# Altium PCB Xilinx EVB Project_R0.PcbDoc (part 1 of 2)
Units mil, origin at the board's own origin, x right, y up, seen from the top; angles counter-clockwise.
Board outline 8120 x 5778 mil, 6 copper layers (Top Layer, Mid-Layer 1, Mid-Layer 2, Mid-Layer 3, Mid-Layer 4, Bottom Layer); 283 components, 125 nets, 1037 pads, 1290 vias.
Unrouted connection lines stored in the file: 1.
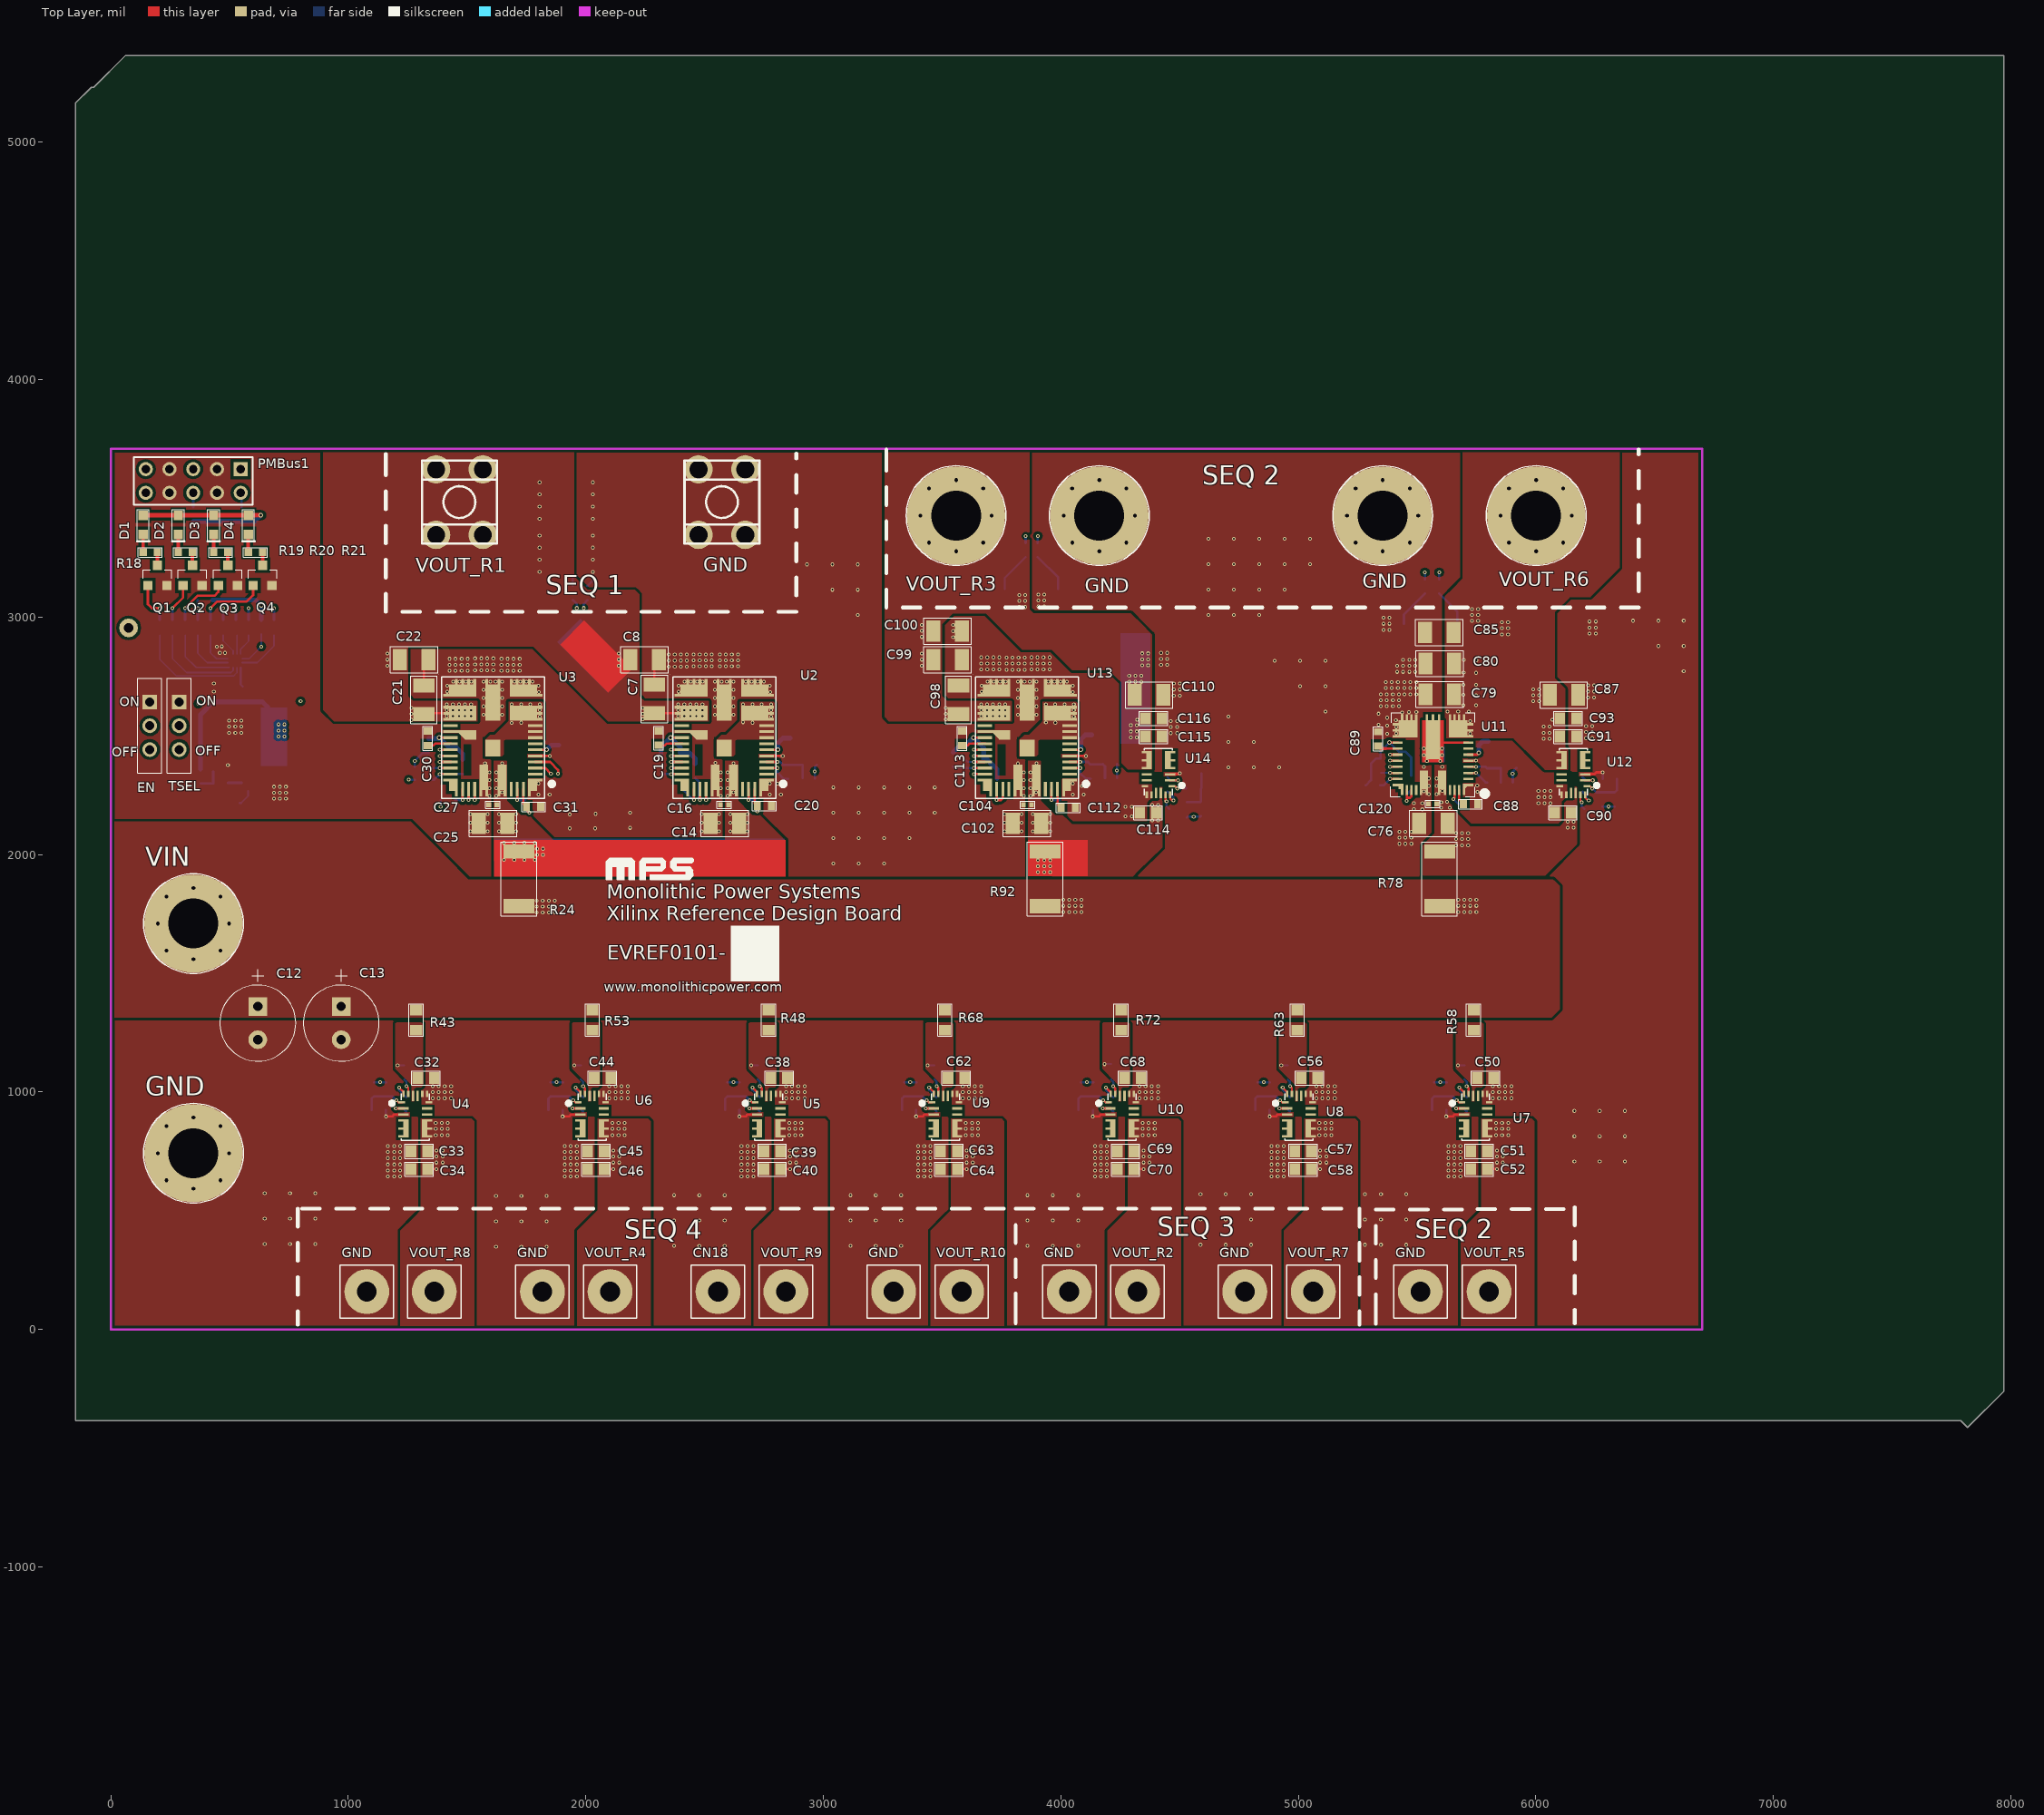
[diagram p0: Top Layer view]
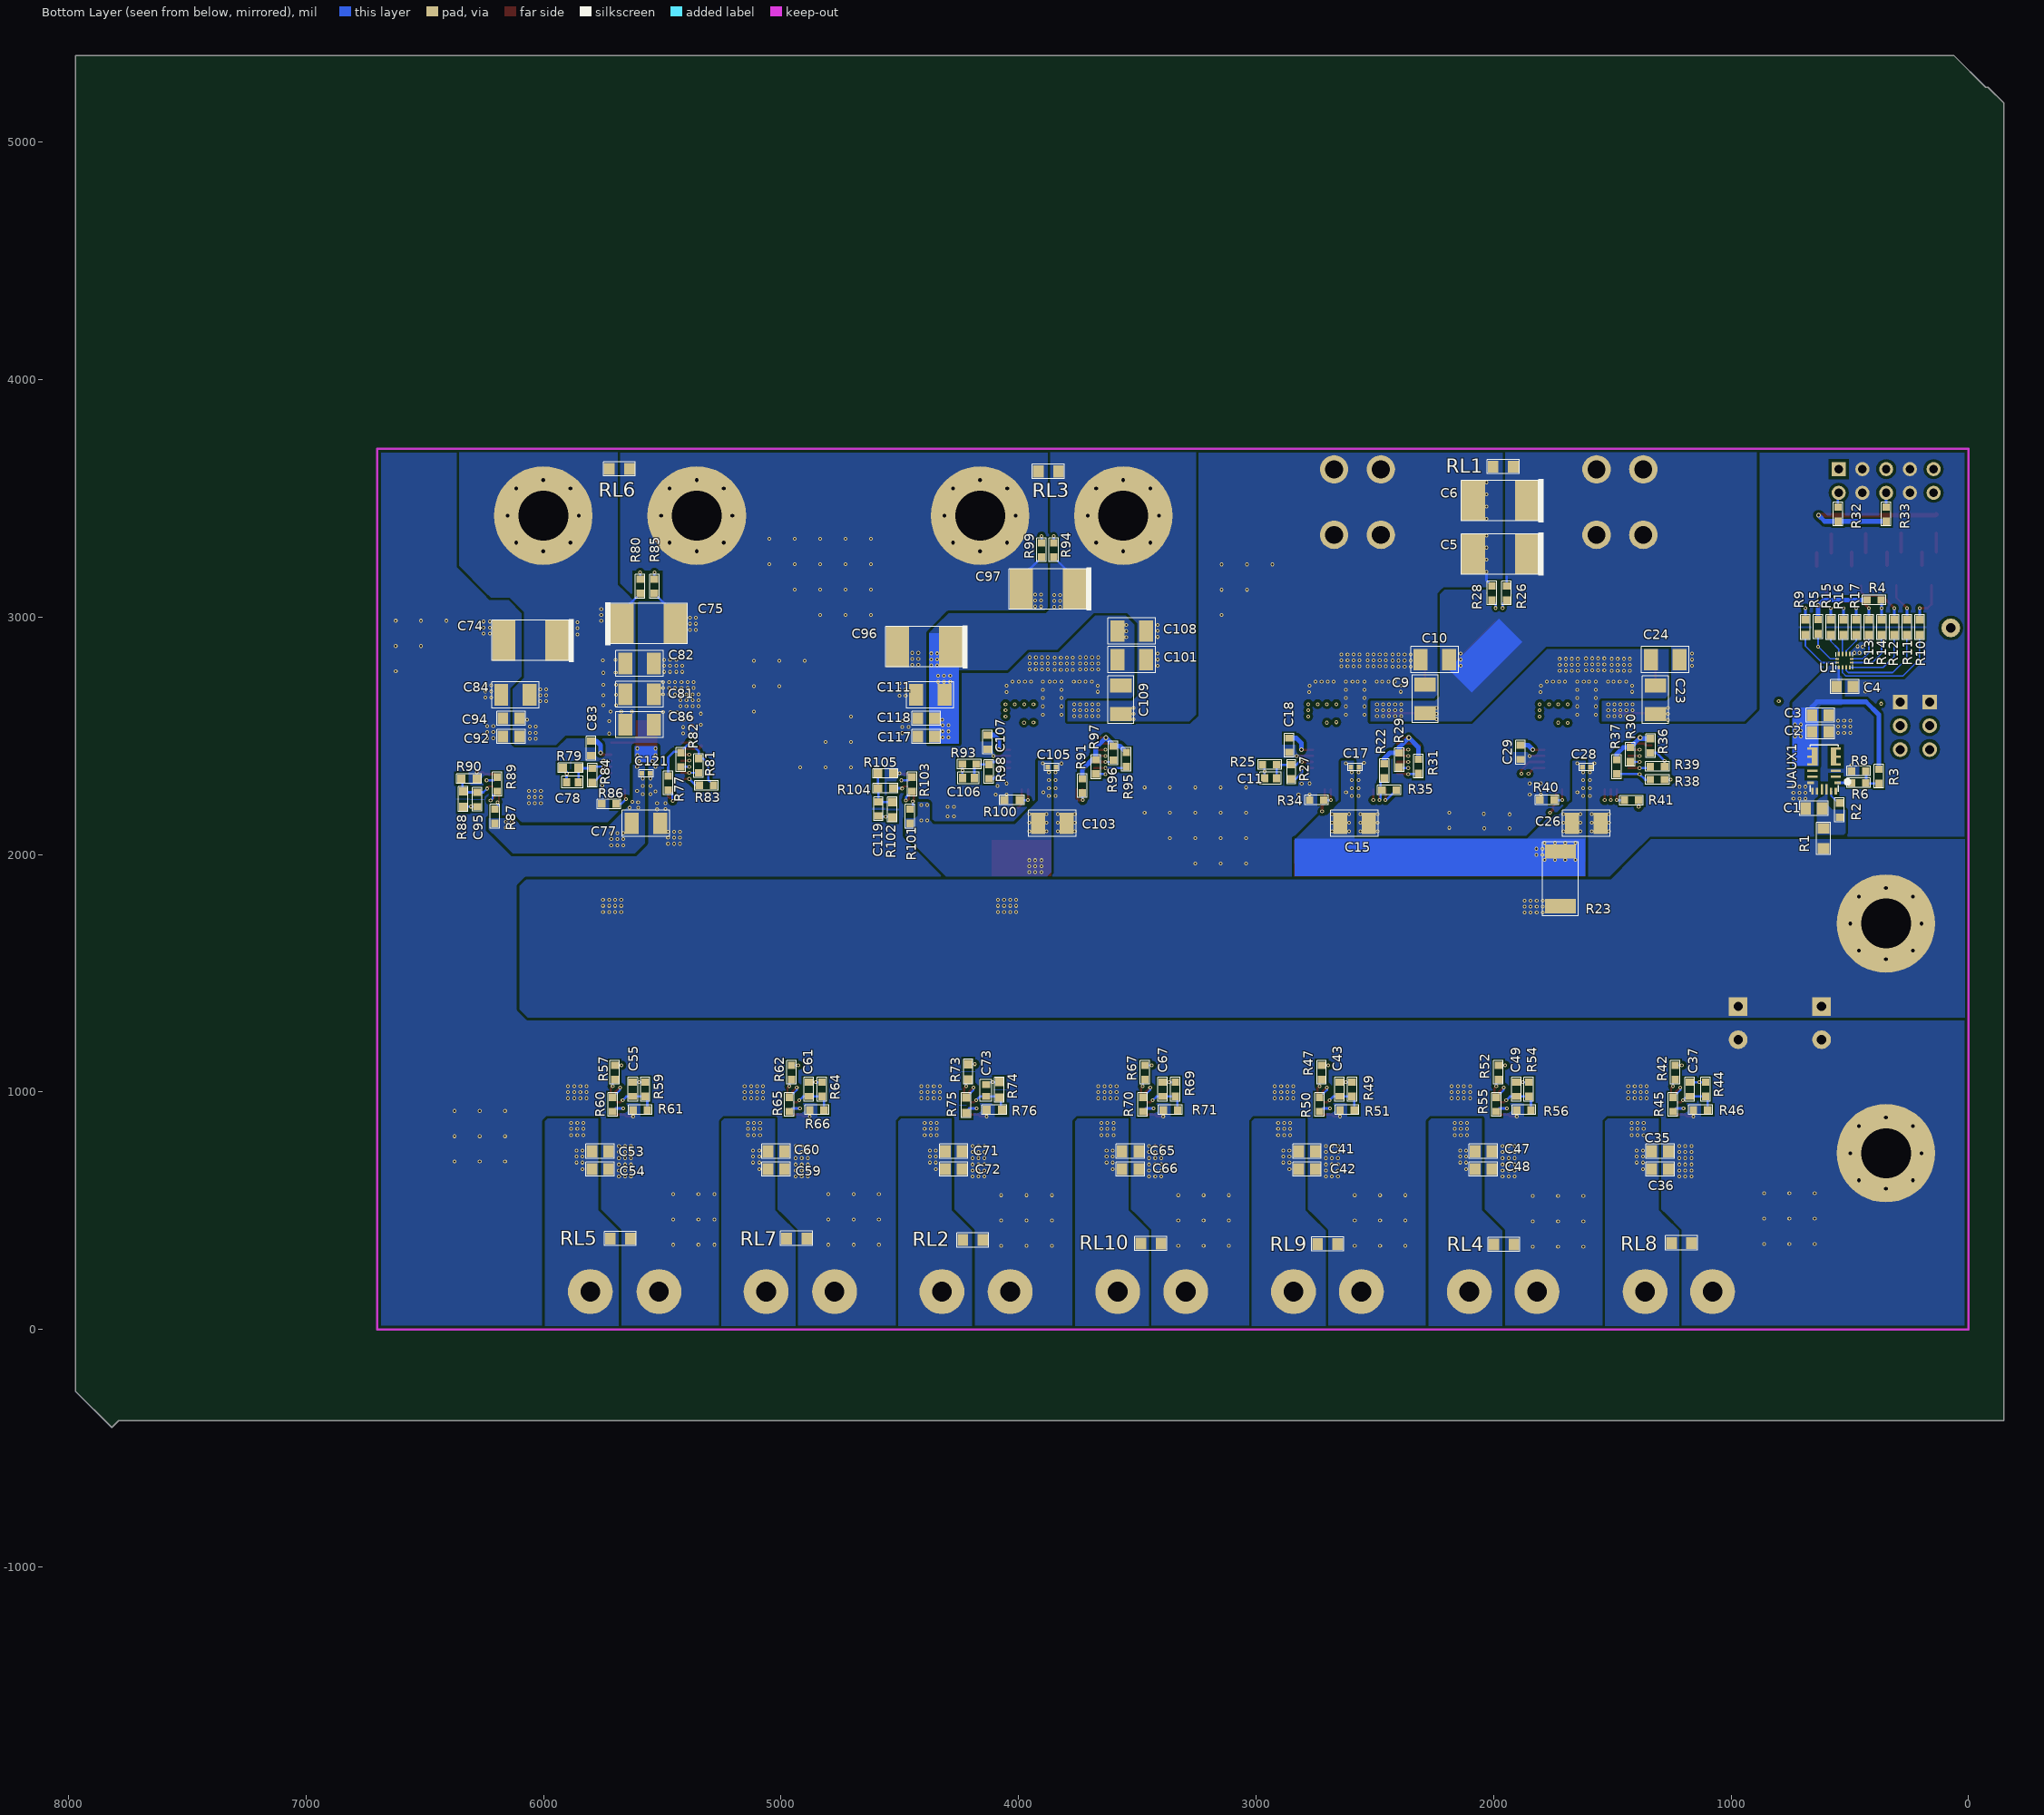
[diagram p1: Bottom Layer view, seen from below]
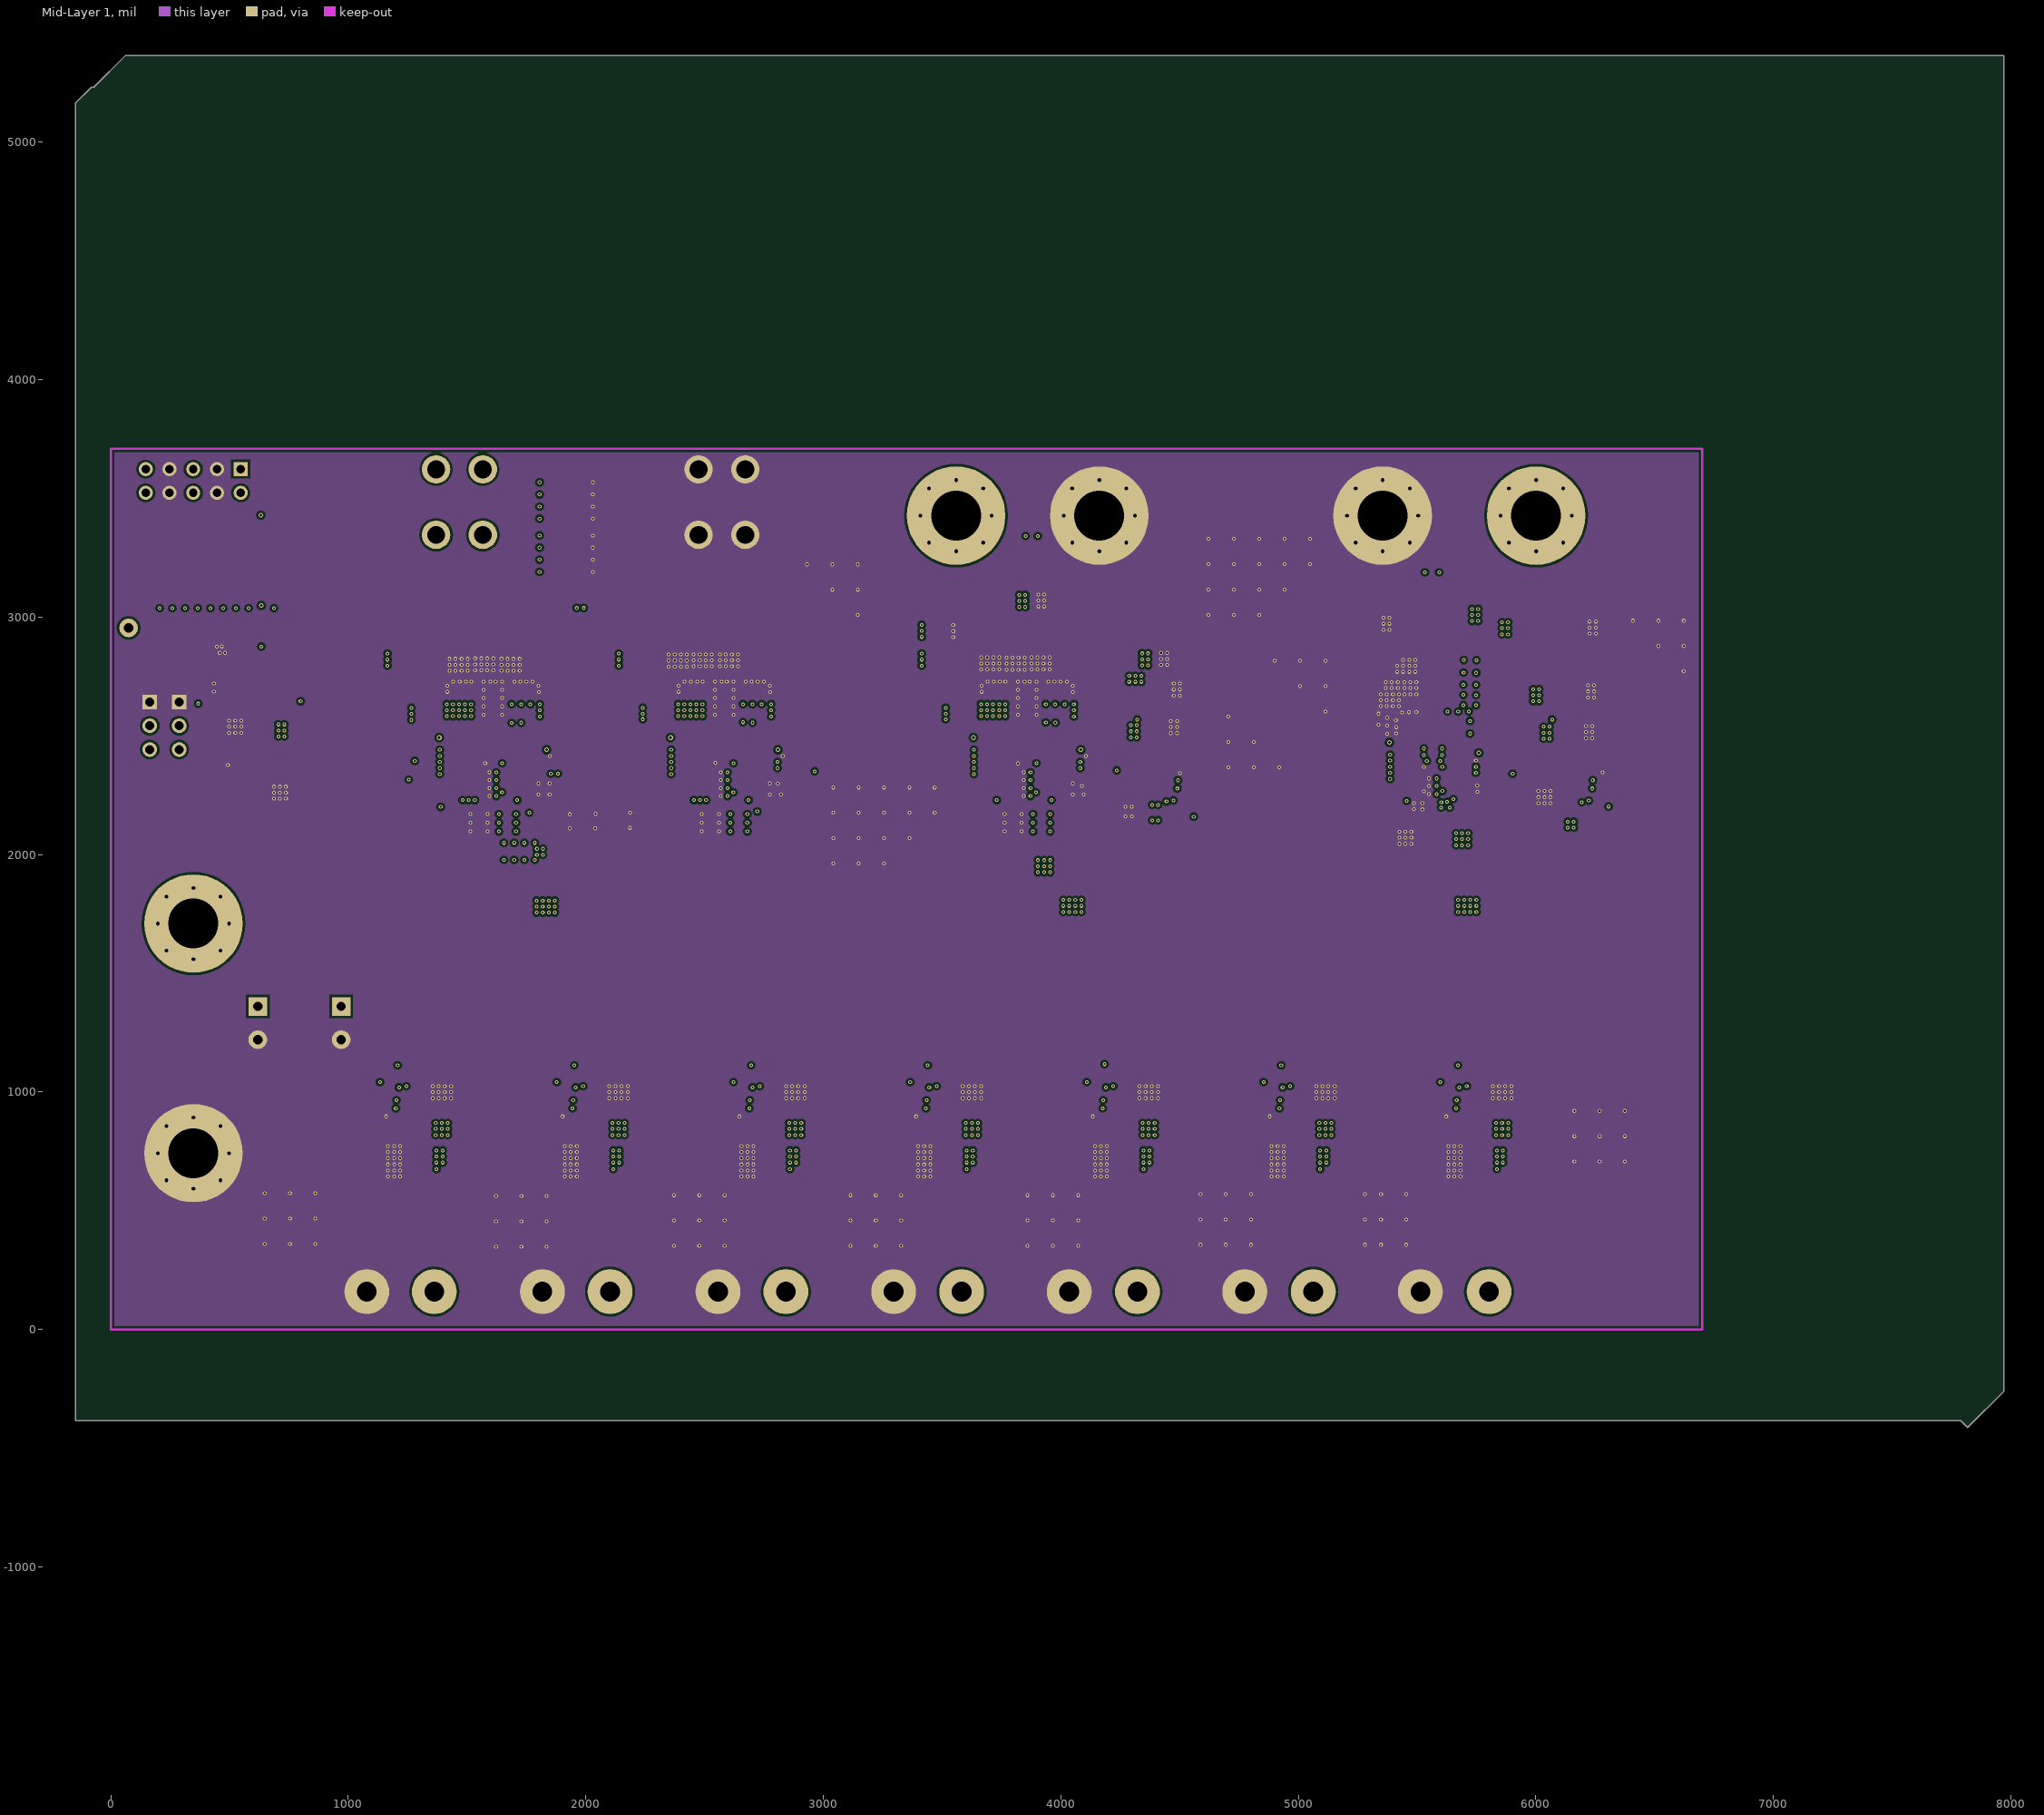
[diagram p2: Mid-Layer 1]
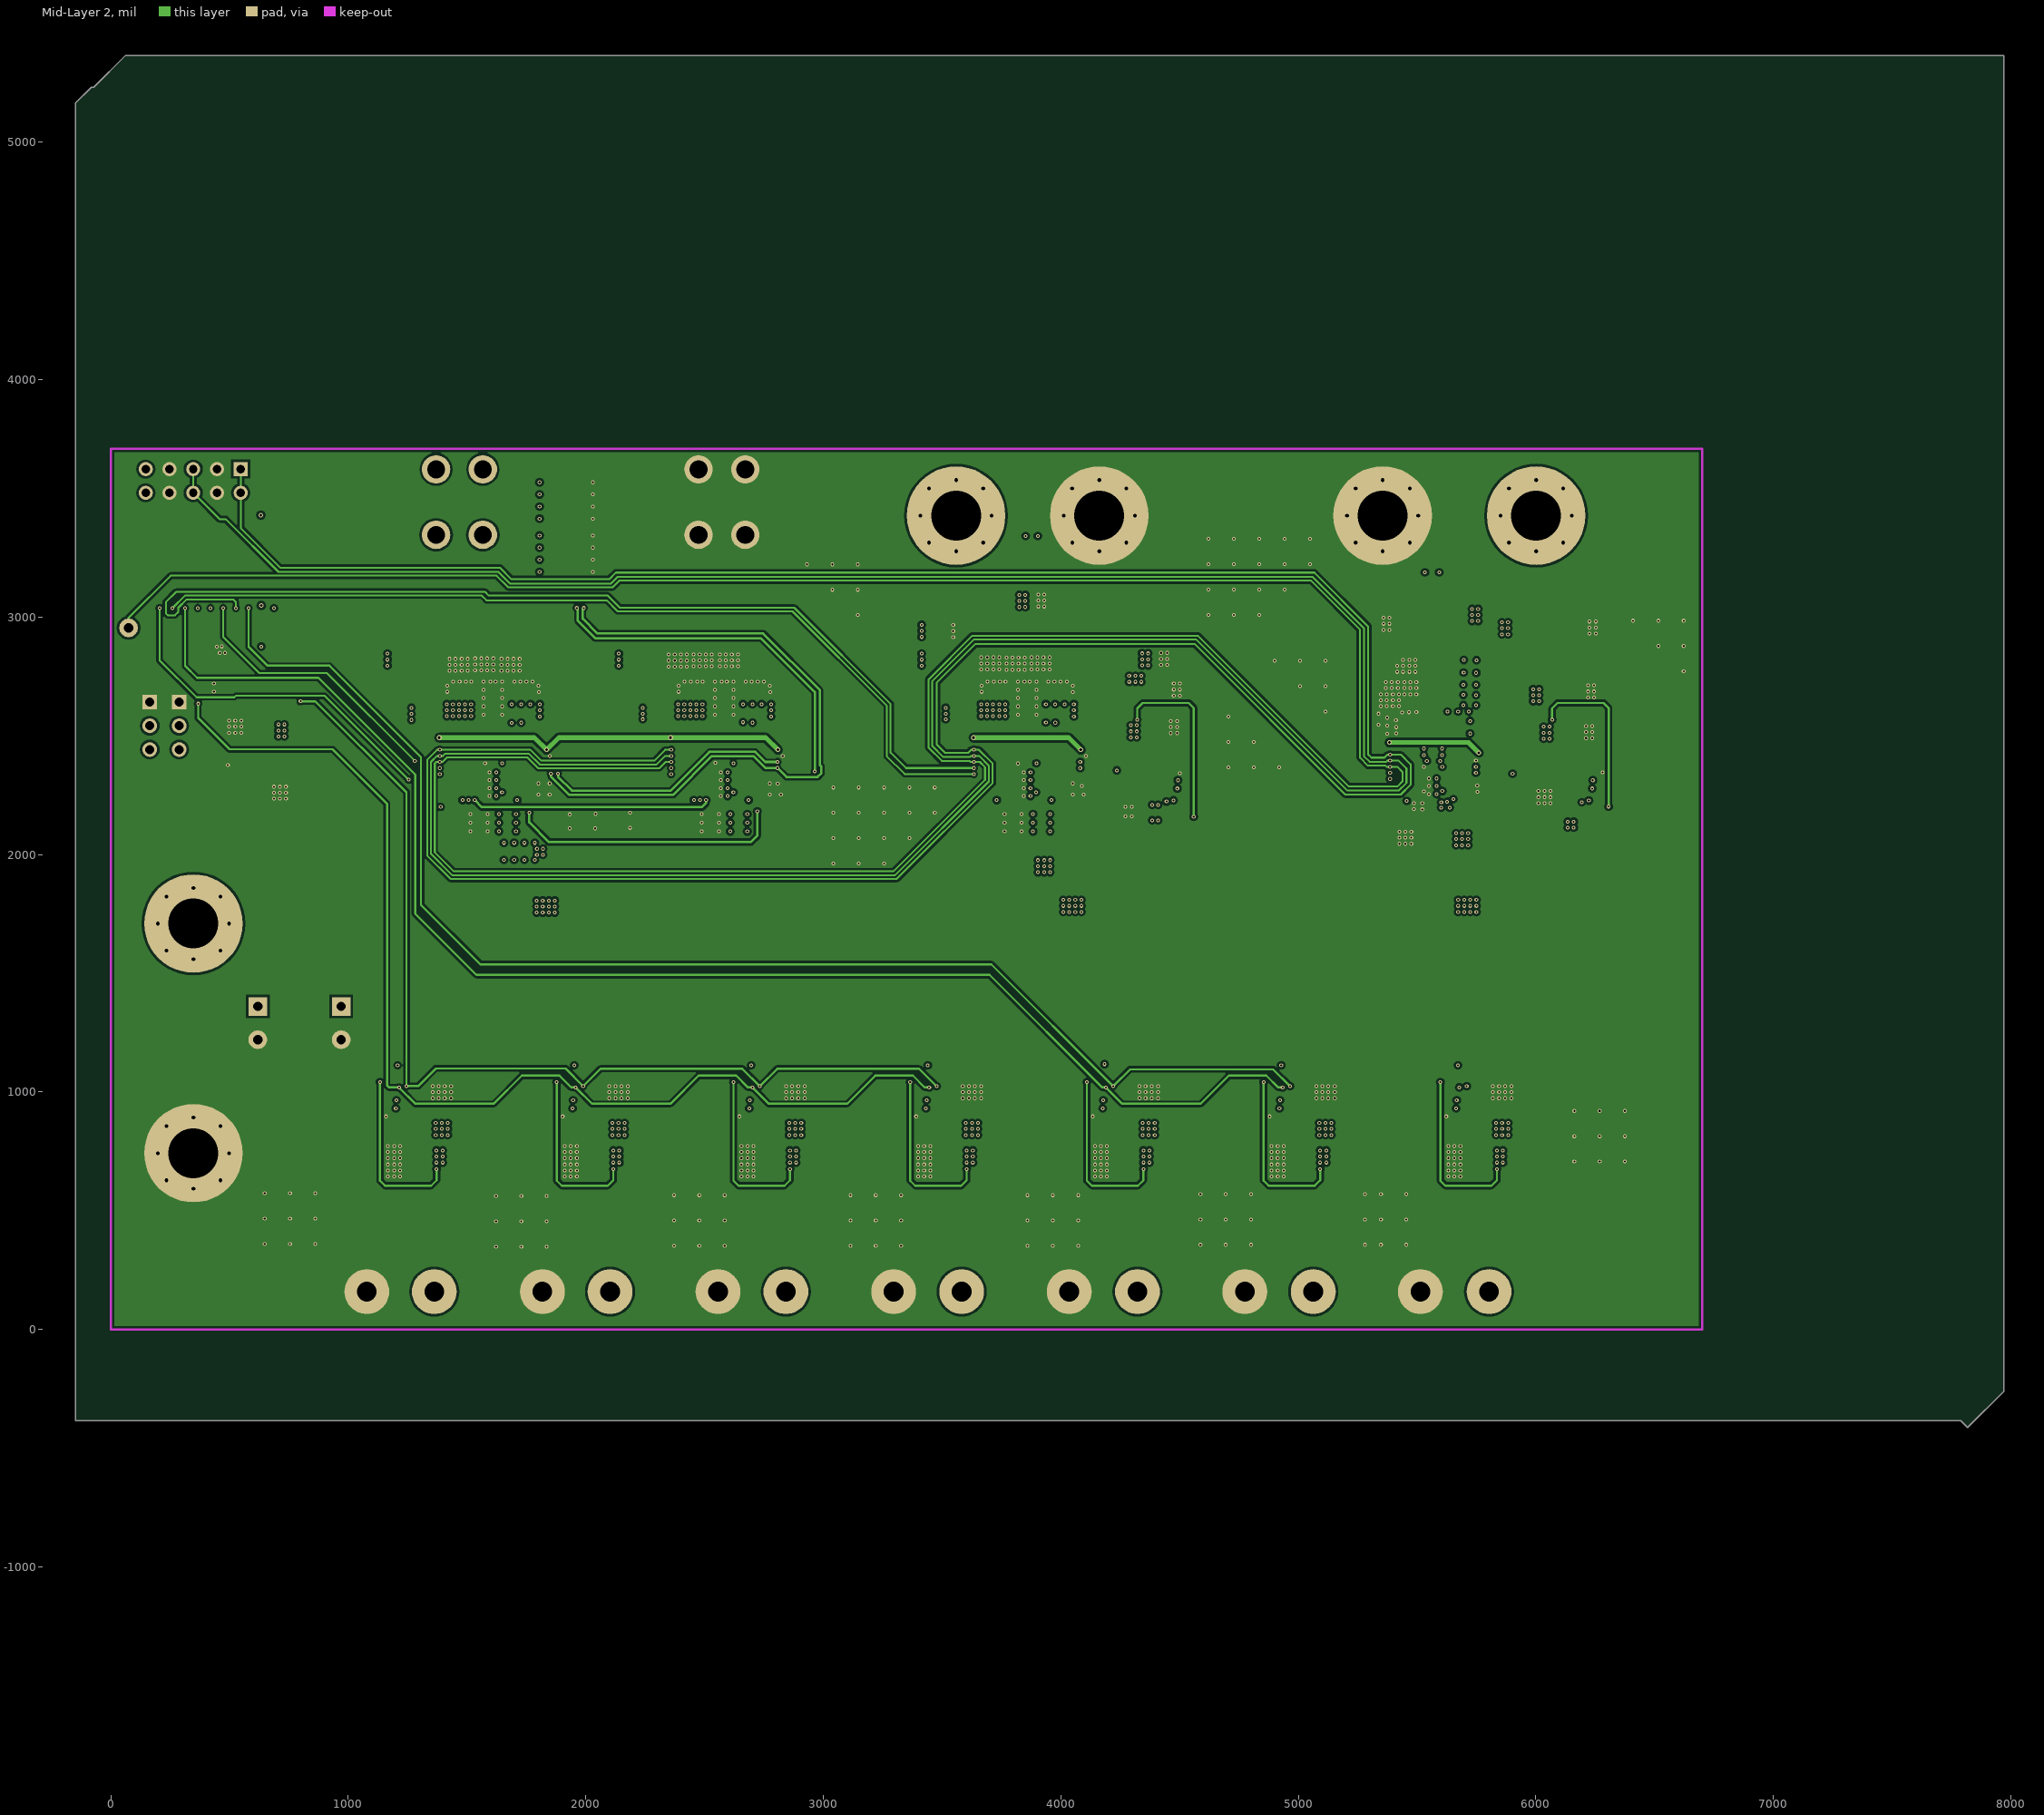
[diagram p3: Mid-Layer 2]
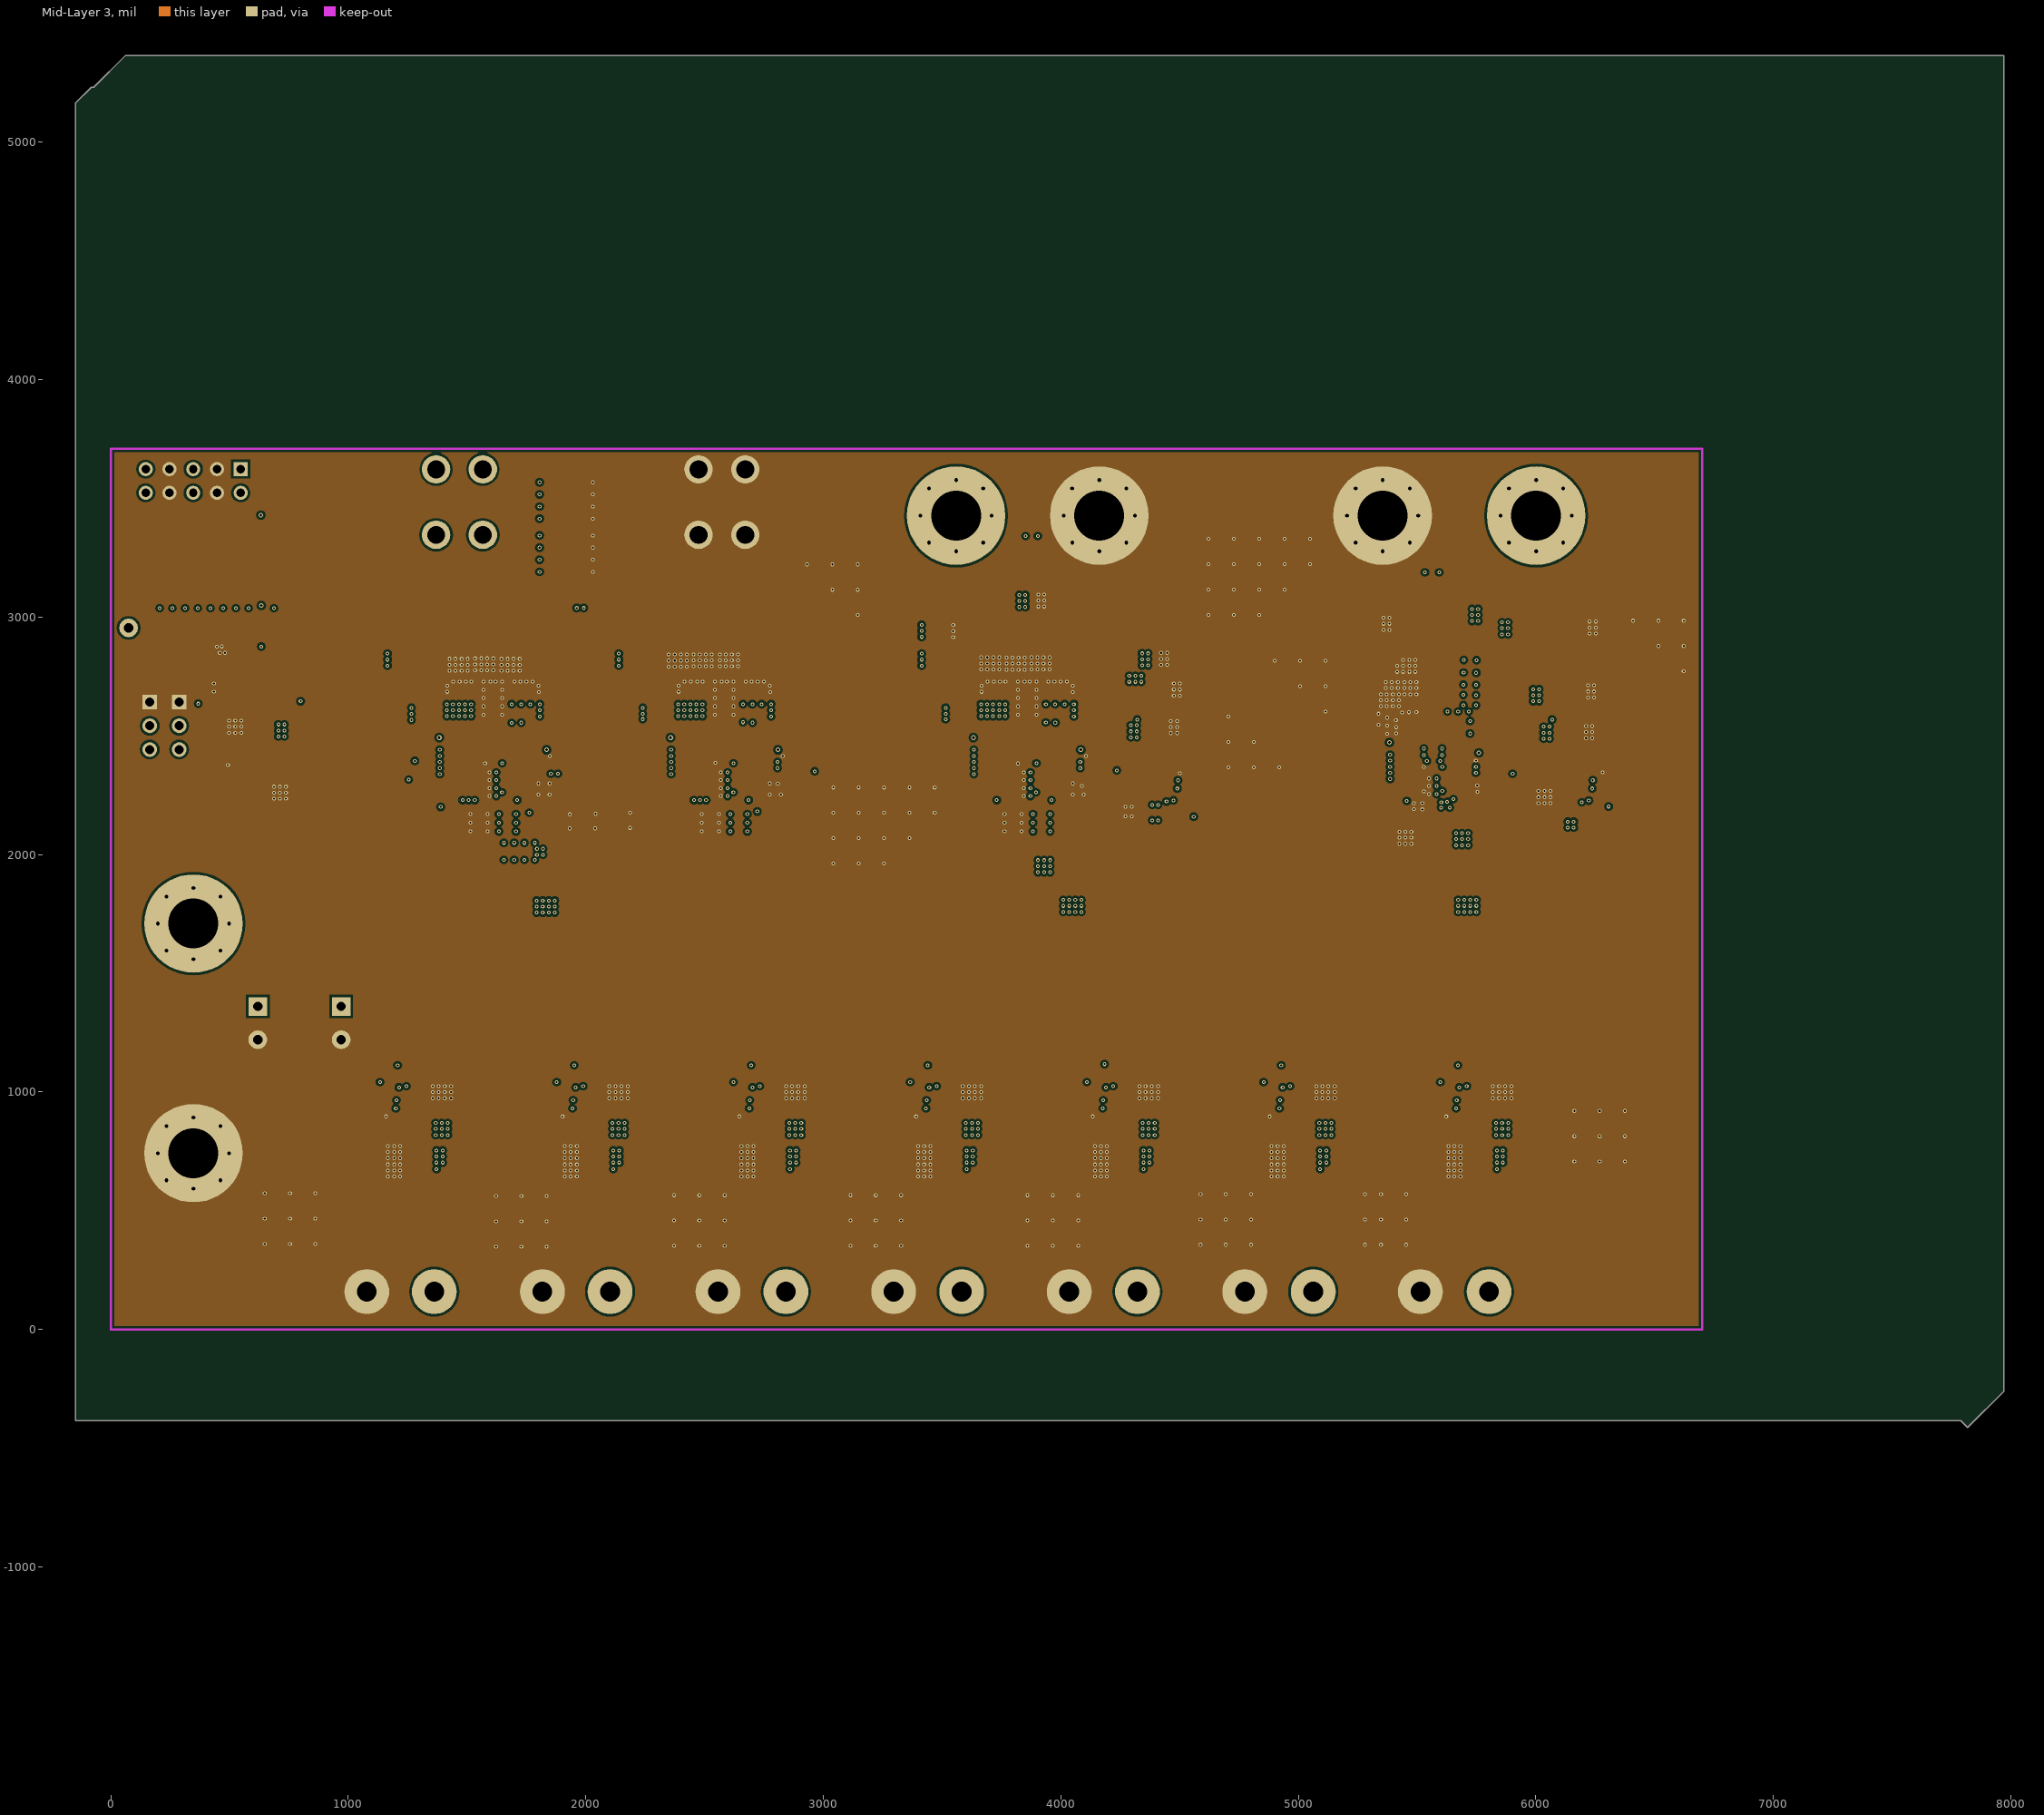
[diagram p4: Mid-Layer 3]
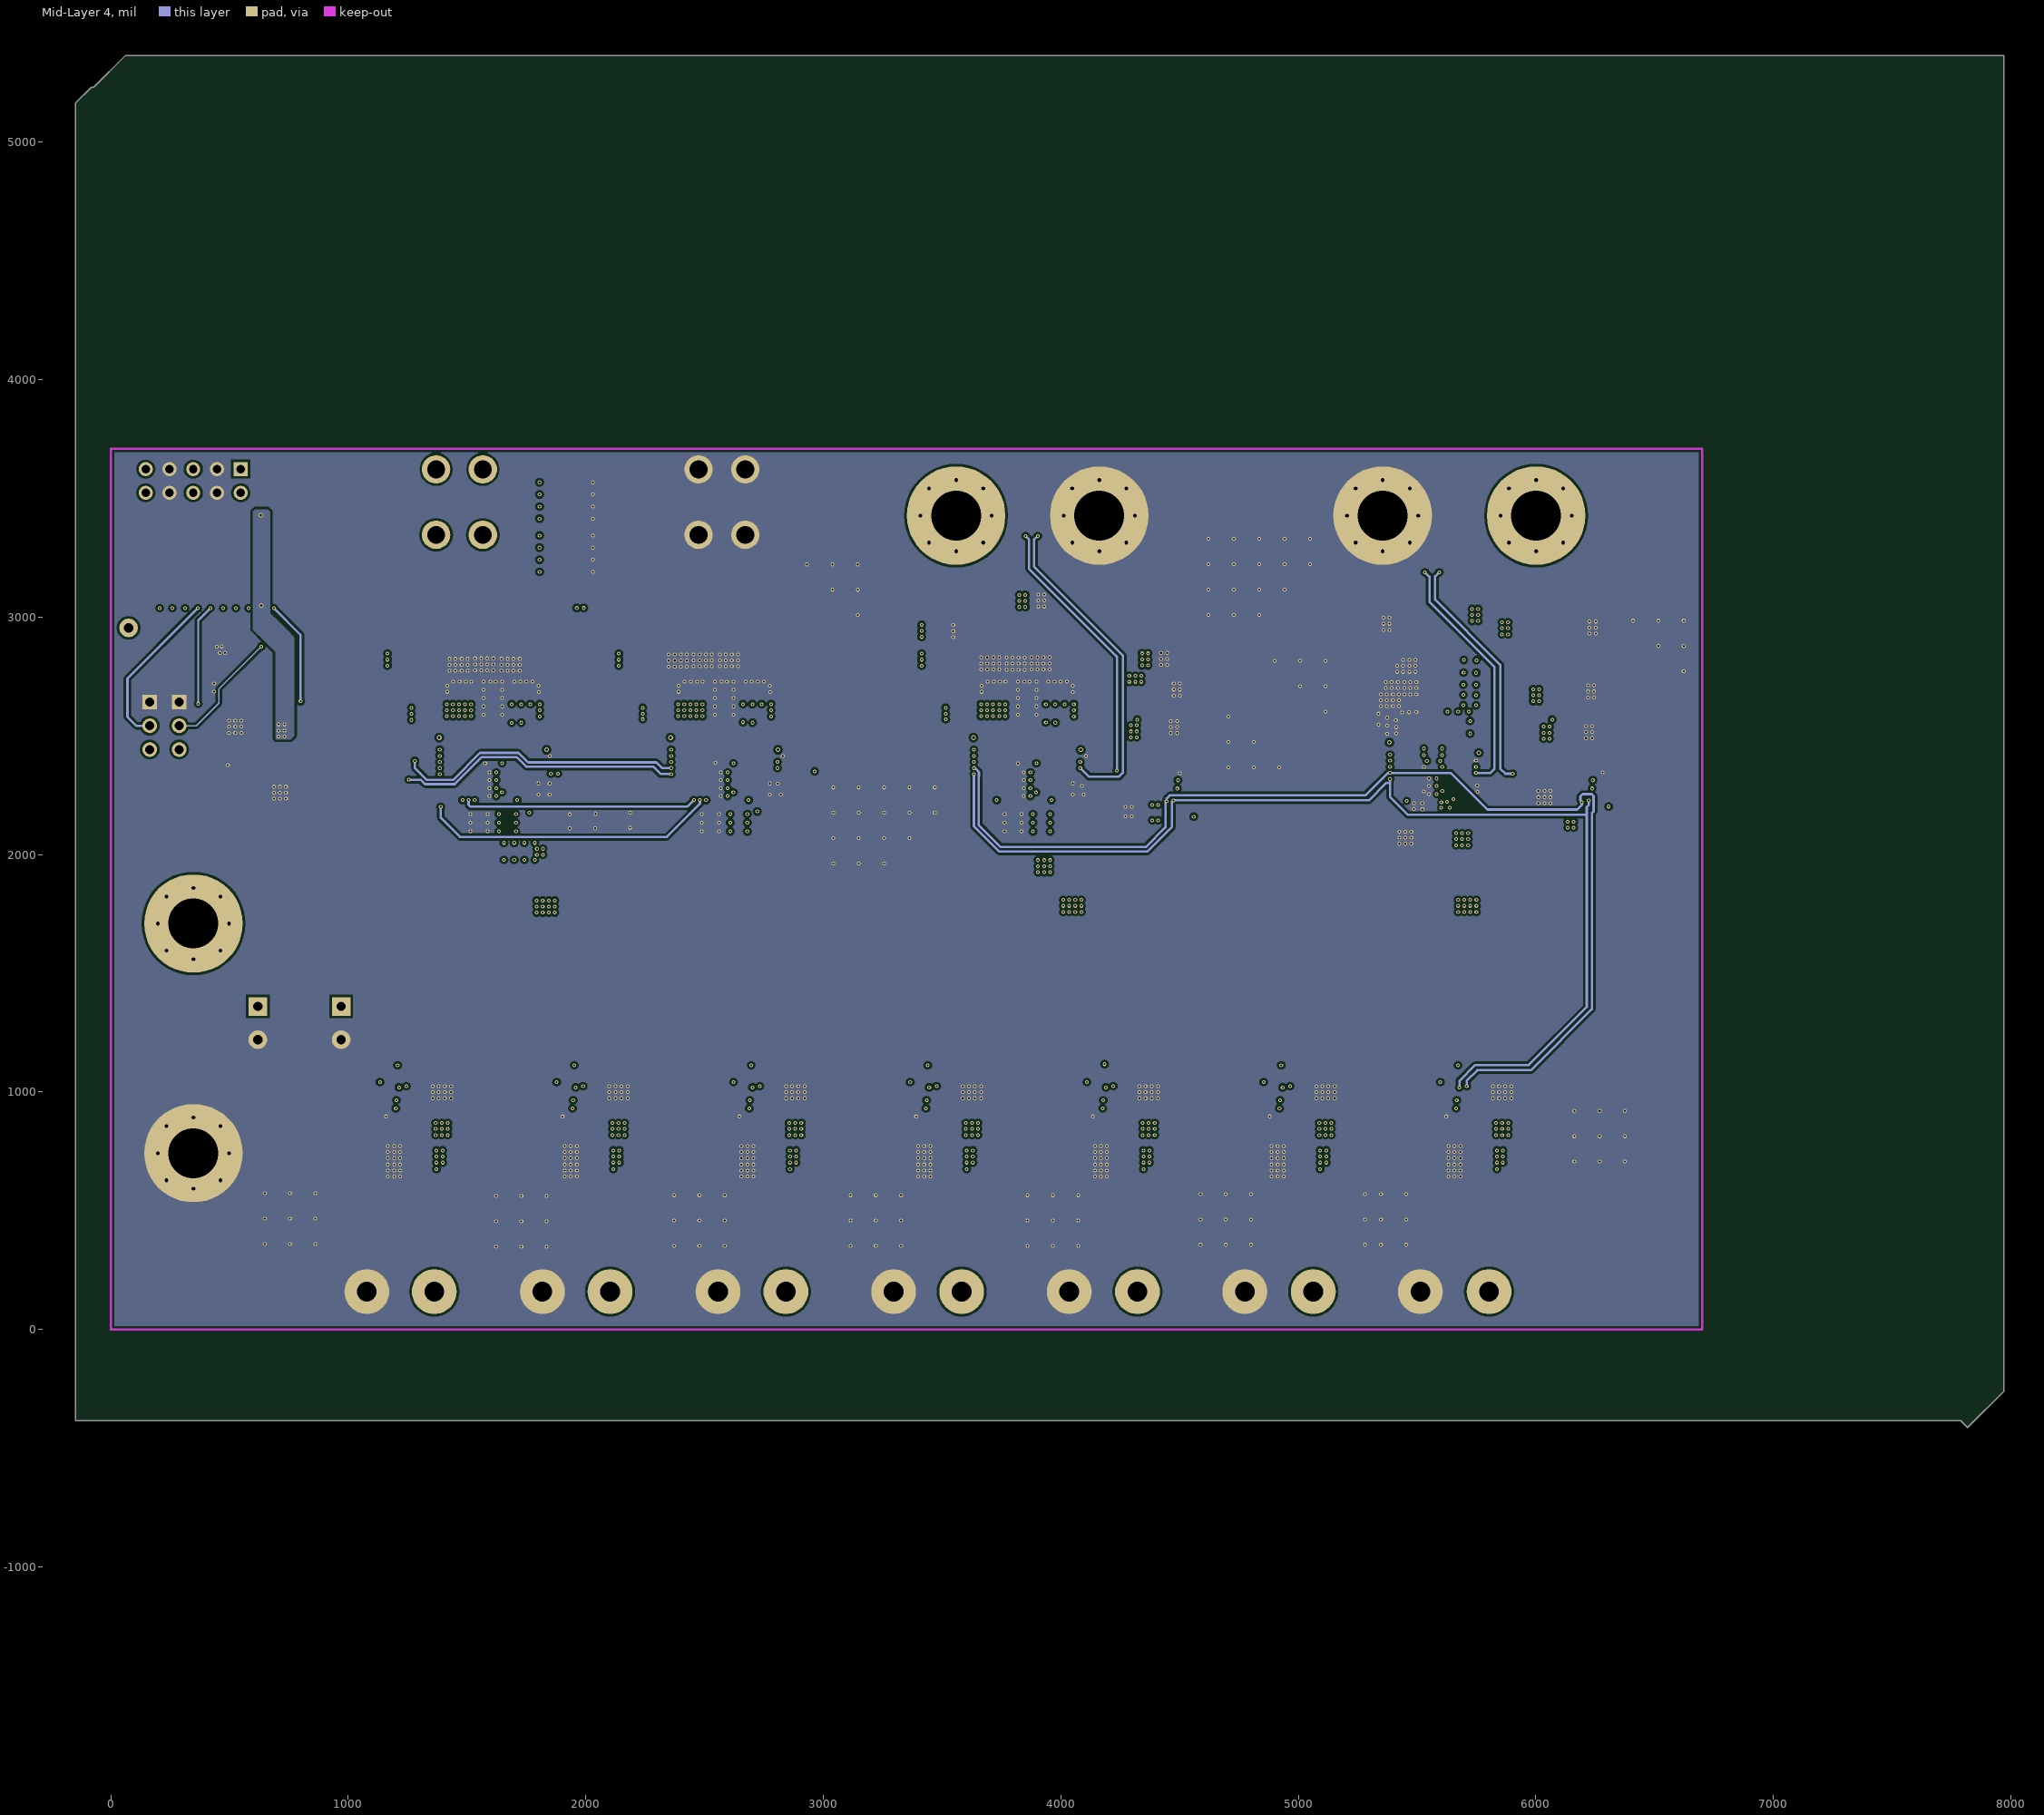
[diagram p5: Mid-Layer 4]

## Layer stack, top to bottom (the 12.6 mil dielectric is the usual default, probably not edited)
Top Layer: signal copper 1.4
Dielectric: core 12.6, FR-4, Dk 4.8
Mid-Layer 1: signal copper 1.4
Dielectric: prepreg 12.6, FR-4, Dk 4.8
Mid-Layer 2: signal copper 1.4
Dielectric: core 12.6, FR-4, Dk 4.8
Mid-Layer 3: signal copper 1.4
Dielectric: prepreg 12.6, FR-4, Dk 4.8
Mid-Layer 4: signal copper 1.4
Dielectric: core 12.6, FR-4, Dk 4.8
Bottom Layer: signal copper 1.4

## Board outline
-82,5230.9 -149,5163.9 -149,-384.1 7789,-384.1 7818,-413.1 7971,-260.1 7971,5364.9 62,5364.9 -72,5230.9

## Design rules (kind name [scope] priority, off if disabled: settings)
Clearance [All] p1: gap=7
ComponentClearance [All] p1: gap=0 collisioncheckmode=3 verticalgap=0 showdistances=FALSE
HoleSize [All] p1: absolutevalues=TRUE maxlimit=10000 minlimit=1 maxpercent=80.000 minpercent=20.000
HoleToHoleClearance [All] p1: gap=0 allowstackedmicrovias=TRUE
MinimumSolderMaskSliver [All] p1: minsoldermaskwidth=0
PlaneConnect [All] p1: planeconnectstyle=Direct reliefexpansion=20 reliefentries=4 reliefconductorwidth=10 reliefairgap=10
PolygonConnect [All] p1: connectstyle=Direct reliefconductorwidth=10 reliefentries=4 polygonreliefangle="90 Angle"
RoutingVias [All] p1: holewidth=10 width=20 viastyle="Through Hole" minholewidth=10 minwidth=20 maxholewidth=10 maxwidth=500
SilkToSilkClearance [All] p1: silktosilkclearance=0
SilkscreenOverComponentPads [All] p1: minsilkscreentomaskgap=0
SolderMaskExpansion [All] p1: expansion=2
Width [All] p1: maxlimit=100 minlimit=3 preferedwidth=10
21 further rules are at their usual default settings.

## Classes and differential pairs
component class P5_Rail_6: C74 C75 C76 C77 C78 C79 C80 C81 C82 C83 C84 C85 C86 C87 C88 C89 C90 C91 C92 C93 C94 C95 C120 C121 GND R77 R78 R79 R80 R81 R82 R83 R84 R85 R86 R87 R88 R89 R90 U11 U12 VOUT_R6
component class P1_Rail1: C5 C6 C7 C8 C9 C10 C11 C12 C13 C14 C15 C16 C17 C18 C19 C20 C21 C22 C23 C24 C25 C26 C27 C28 C29 C30 C31 GND PMBus1 R22 R23 R24 R25 R26 R27 R28 R29 R30 R31 R32 R33 R34 R35 R36 R37 R38 R39 R40 R41 U2 U3 VIN VOUT_R1
component class P2_Rail_2: C68 C69 C70 C71 C72 C73 CN18 R72 R73 R74 R75 R76 U10 VOUT_R2
component class P4_Rail_4_and_Rail_5: C44 C45 C46 C47 C48 C49 C50 C51 C52 C53 C54 C55 GND R52 R53 R54 R55 R56 R57 R58 R59 R60 R61 U6 U7 VOUT_R4 VOUT_R5
component class P6_Rail_7_and_Rail_10: C56 C57 C58 C59 C60 C61 C62 C63 C64 C65 C66 C67 GND R62 R63 R64 R65 R66 R67 R68 R69 R70 R71 U8 U9 VOUT_R7 VOUT_R10
component class P7_Rail_8_and_Rail_9: C32 C33 C34 C35 C36 C37 C38 C39 C40 C41 C42 C43 GND R42 R43 R44 R45 R46 R47 R48 R49 R50 R51 U4 U5 VOUT_R8 VOUT_R9
component class P8_Aux_Circuit: C1 C2 C3 C4 D1 D2 D3 D4 EN Q1 Q2 Q3 Q4 R1 R2 R3 R4 R5 R6 R8 R9 R10 R11 R12 R13 R14 R15 R16 R17 R18 R19 R20 R21 RL1 RL2 RL3 RL4 RL5 RL6 RL7 RL8 RL9 RL10 TSEL U1 UAUX1
component class "P3_Rail 3": C96 C97 C98 C99 C100 C101 C102 C103 C104 C105 C106 C107 C108 C109 C110 C111 C112 C113 C114 C115 C116 C117 C118 C119 GND R91 R92 R93 R94 R95 R96 R97 R98 R99 R100 R101 R102 R103 R104 R105 U13 U14 VOUT_R7

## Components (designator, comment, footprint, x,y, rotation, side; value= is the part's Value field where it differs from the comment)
C1 "22uF/CAP0805" CAP0805 686,2194 r180 bottom
C2 "NS" CAP0805 589,2516 r0 bottom
C3 "22uF/CAP0805" CAP0805 589,2586 r0 bottom
C4 "22uF/CAP0805" CAP0805 486,2707 r0 bottom
C5 "POSCAP/D2-D4" POSCAP/D2 1861,3265 r0 bottom
C6 "POSCAP/D2-D4" POSCAP/D2 1861,3490 r0 bottom
C7 "100uF" CAP/1210 2289,2715 r270 top
C8 "100uF" CAP/1210 2308,2820 r180 top
C9 "100uF" CAP/1210 2289,2715 r270 bottom
C10 "100uF" CAP/1210 2308,2820 r180 bottom
C11 "4.7nF" CAP0603 2914,2321 r0 bottom
C12 "220uF" CAP/OD8.0P3.5 619,1360 r270 top
C13 "220uF" CAP/OD8.0P3.5 970,1360 r270 top
C14 "22uF" CAP/1210 2525,2131 r0 top
C15 "22uF" CAP/1210 2525,2131 r0 bottom
C16 "0.1uF" CAP0402 2566,2209 r0 top
C17 "0.1uF" CAP0402 2566,2368 r0 bottom
C18 "5.6pF/CAP0603" CAP/0603 2861,2430 r90 bottom
C19 "4.7uF" CAP/0603 2307,2520 r270 top
C20 "1uF" CAP/0603 2782,2205 r180 top
C21 "100uF" CAP/1210 1318.64,2711.36 r270 top
C22 "100uF" CAP/1210 1337.64,2820 r180 top
C23 "100uF" CAP/1210 1318.64,2711.36 r270 bottom
C24 "100uF" CAP/1210 1337.64,2820 r180 bottom
C25 "22uF" CAP/1210 1550,2131 r0 top
C26 "22uF" CAP/1210 1550,2131 r0 bottom
C27 "0.1uF" CAP0402 1591,2209 r0 top
C28 "0.1uF" CAP0402 1591,2368 r0 bottom
C29 "4.7uF" CAP/0603 1886,2400 r90 bottom
C30 "5.6pF/CAP0603" CAP/0603 1335,2519 r270 top
C31 "5.6pF/CAP0603" CAP/0603 1810,2201 r180 top
C32 "22uF/CAP0805" CAP0805 1362,1058 r180 top
C33 "22uF/CAP0805" CAP0805 1264,750 r0 top
C34 "22uF/CAP0805" CAP0805 1264,675 r0 top
C35 "22uF/CAP0805" CAP0805 1264,750 r0 bottom
C36 "22uF/CAP0805" CAP0805 1264,675 r0 bottom
C37 "5.6pF/CAP0603" CAP/0603 1173.5,981 r90 bottom
C38 "22uF/CAP0805" CAP0805 2849,1059 r180 top
C39 "NS" CAP0805 2750,750 r0 top
C40 "22uF/CAP0805" CAP0805 2750,675 r0 top
C41 "NS" CAP0805 2750,750 r0 bottom
C42 "NS" CAP0805 2750,675 r0 bottom
C43 "5.6pF/CAP0603" CAP/0603 2648.67,981 r90 bottom
C44 "22uF/CAP0805" CAP0805 2105,1058 r180 top
C45 "Cap" CAP0805 2008,750 r0 top
C46 "22uF" CAP0805 2008,675 r0 top
C47 "Cap" CAP0805 2008,750 r0 bottom
C48 "Cap" CAP0805 2008,675 r0 bottom
C49 "5.6pF/CAP0603" CAP/0603 1904.58,981 r90 bottom
C50 "22uF/CAP0805" CAP0805 5823,1058 r180 top
C51 "NS" CAP0805 5726,750 r0 top
C52 "NS" CAP0805 5726,675 r0 top
C53 "22uF/CAP0805" CAP0805 5726,750 r0 bottom
C54 "NS" CAP0805 5726,675 r0 bottom
C55 "5.6pF/CAP0603" CAP/0603 5625,981 r90 bottom
C56 "22uF/CAP0805" CAP0805 5082,1058 r180 top
C57 "NS" CAP0805 4985,750 r0 top
C58 "22uF/CAP0805" CAP0805 4985,675 r0 top
C59 "NS" CAP0805 4985,675 r0 bottom
C60 "NS" CAP0805 4985,750 r0 bottom
C61 "5.6pF/CAP0603" CAP/0603 4883,981 r90 bottom
C62 "22uF/CAP0805" CAP0805 3595,1058 r180 top
C63 "NS" CAP0805 3494,750 r0 top
C64 "22uF/CAP0805" CAP0805 3494,675 r0 top
C65 "NS" CAP0805 3494,750 r0 bottom
C66 "NS" CAP0805 3494,675 r0 bottom
C67 "5.6pF/CAP0603" CAP/0603 3392.75,981 r90 bottom
C68 "22uF/0805" CAP0805 4338,1058 r180 top
C69 "CAP0805" CAP0805 4238,750 r0 top
C70 "22uF/0805" CAP0805 4238,675 r0 top
C71 "22uF/0805" CAP0805 4238,750 r0 bottom
C72 "22uF/0805" CAP0805 4238,675 r0 bottom
C73 "5.6pF/0603" CAP0603 4136.83,981 r90 bottom
C74 "POSCAP/D2-D4" POSCAP/D2 5943,2901 r0 bottom
C75 "POSCAP/D2-D4" POSCAP/D2 5669,2972 r180 bottom
C76 "47uF" CAP/1210 5509,2131 r0 top
C77 "47uF" CAP/1210 5509,2131 r0 bottom
C78 "10nF" CAP0603 5853,2304 r0 bottom
C79 "100uF" CAP/1210 5535,2674 r0 top
C80 "100uF" CAP/1210 5535,2804.5 r0 top
C81 "100uF" CAP/1210 5535,2674 r0 bottom
C82 "100uF" CAP/1210 5535,2804.5 r0 bottom
C83 "5.6pF/CAP0603" CAP/0603 5799,2417 r90 bottom
C84 "100uF" CAP/1210 6178,2672 r180 bottom
C85 "100uF" CAP/1210 5534,2935 r0 top
C86 "100uF" CAP/1210 5536,2546 r0 bottom
C87 "100uF" CAP/1210 6178,2672 r180 top
C88 "5.6pF/CAP0603" CAP/0603 5755,2213 r180 top
C89 "5.6pF/CAP0603" CAP/0603 5336,2517 r270 top
C90 "22uF/CAP0805" CAP0805 6079,2176 r0 top
C91 "22uF/CAP0805" CAP0805 6171,2497 r180 top
C92 "NS" CAP0805 6171,2497 r180 bottom
C93 "22uF/CAP0805" CAP0805 6171,2573 r180 top
C94 "22uF/CAP0805" CAP0805 6171,2573 r180 bottom
C95 "5.6pF/CAP0603" CAP/0603 6279.5,2261.83 r270 bottom
C96 "POSCAP/D2-D4" POSCAP/D2 4285,2874 r0 bottom
C97 "POSCAP/D2-D4" POSCAP/D2 3764,3118 r0 bottom
C98 "100uF" CAP/1210 3569,2711 r270 top
C99 "100uF" CAP/1210 3583,2820 r180 top
C100 "100uF" CAP/1210 3583,2941 r180 top
C101 "100uF" CAP/1210 3583,2820 r180 bottom
C102 "47uF" CAP/1210 3798,2131 r0 top
C103 "47uF" CAP/1210 3798,2131 r0 bottom
C104 "5.6pF/CAP0603" CAP0402 3842,2209 r0 top
C105 "5.6pF/CAP0603" CAP0402 3842,2368 r0 bottom
C106 "10nF" CAP0603 4186,2322 r0 bottom
C107 "5.6pF/CAP0603" CAP/0603 4130,2443 r90 bottom
C108 "100uF" CAP/1210 3583,2941 r180 bottom
C109 "100uF" CAP/1210 3569,2712 r270 bottom
C110 "100uF" CAP/1210 4432,2672 r180 top
C111 "100uF" CAP/1210 4432,2672 r180 bottom
C112 "5.6pF/CAP0603" CAP/0603 4061,2197 r180 top
C113 "5.6pF/CAP0603" CAP/0603 3585,2519 r270 top
C114 "Cap" CAP0805 4332,2176 r0 top
C115 "NS" CAP0805 4426,2497 r180 top
C116 "Cap" CAP0805 4426,2573 r180 top
C117 "Cap" CAP0805 4424,2497 r180 bottom
C118 "Cap" CAP0805 4424,2573 r180 bottom
C119 "22pF/CAP0603" CAP/0603 4590,2222 r270 bottom
C120 "5.6pF/CAP0603" CAP0402 5548,2213 r0 top
C121 "5.6pF/CAP0603" CAP0402 5551,2341 r0 bottom
CN18 "TP2MM" TP2MM 2556.67,159 r0 top
D1 "LED/SMD/0805" LED/SMD/0805 136,3348 r90 top
D2 "LED/SMD/0805" LED/SMD/0805 284,3348 r90 top
D3 "LED/SMD/0805" LED/SMD/0805 433,3348 r90 top
D4 "LED/SMD/0805" LED/SMD/0805 579,3348 r90 top
EN "SWITCH_SPDT_WE" JUMPER/3PIN-WE450301014042 164,2642 r270 top (schematic designator SW1)
GND "GND" KEYSTONE-7697-75 2573,3484 r0 top (schematic designator CN2)
GND "GND" BANANA-K575 348,742 r0 top (schematic designator CN4)
GND "TP2MM" TP2MM 4035.33,159 r0 top (schematic designator CN6)
GND "TP2MM" TP2MM 1078,159 r0 top (schematic designator CN8)
GND "TP2MM" TP2MM 4774.67,159 r0 top (schematic designator CN14)
GND "TP2MM" TP2MM 1817.33,159 r0 top (schematic designator CN16)
GND "GND" BANANA-K575 4162,3427 r0 top (schematic designator CN22)
GND "TP2MM" TP2MM 3296,159 r0 top (schematic designator CN10)
GND "TP2MM" TP2MM 5514,159 r0 top (schematic designator CN12)
GND "GND" BANANA-K575 5355,3427 r0 top (schematic designator CN20)
PMBus1 "Header 5X2" HDR2X5 547,3623 r180 top
Q1 "ZVN3320/SOT23" ZVN3320/SOT23 196,3178 r0 top
Q2 "ZVN3320/SOT23" ZVN3320/SOT23 344,3178 r0 top
Q3 "ZVN3320/SOT23" ZVN3320/SOT23 493,3178 r0 top
Q4 "ZVN3320/SOT23" ZVN3320/SOT23 639,3178 r0 top
R1 "10m" RES/0805 611,2025 r90 bottom
R2 "100k" RES/0603 543,2157 r90 bottom
R3 "75k" RES/0603 378,2299 r90 bottom
R4 "" RES/0603 368,3072 r0 bottom
R5 "" RES/0603 633.56,2929 r90 bottom
R6 "0" RES/0603 493,2301 r180 bottom
R8 "24k" RES/0603 493,2351 r180 bottom
R9 "10m/RES2512" RES0603 687,2924 r90 bottom
R10 "10m/RES2512" RES0603 206,2989 r270 bottom
R11 "10m/RES2512" RES0603 259.44,2989 r270 bottom
R12 "10m/RES2512" RES0603 312.89,2989 r270 bottom
R13 "10m/RES2512" RES0603 419.78,2989 r270 bottom
R14 "10m/RES2512" RES0603 366.33,2989 r270 bottom
R15 "10m/RES2512" RES0603 580.11,2924 r90 bottom
R16 "10m/RES2512" RES0603 526.67,2924 r90 bottom
R17 "10m/RES2512" RES0603 473.22,2924 r90 bottom
R18 "" RES/0603 196,3273 r180 top
R19 "" RES/0603 344,3273 r180 top
R20 "" RES/0603 493,3273 r180 top
R21 "" RES/0603 639,3273 r180 top
R22 "10k" RES/0603 2460,2322 r90 bottom
R23 "RES2512" RES2512 1718,1782 r90 bottom
R24 "RES2512" RES2512 1718,1782 r90 top
R25 "2.05" RES/0603 2973,2378 r180 bottom
R26 "0ohm" RES/0603 1945,3071 r90 bottom
R27 "4.87k" RES/0603 2852,2318 r90 bottom
R28 "0ohm" RES/0603 2007,3071 r90 bottom
R29 "100k" RES/0603 2397,2428 r270 bottom
R30 "10k" RES/0603 1424,2451 r270 bottom
R31 "10k" RES/0603 2316,2401 r270 bottom
R32 "10k" RES/0603 550,3403 r90 bottom
R33 "10k" RES/0603 347,3463 r270 bottom
R34 "0" RES/0603 2715,2229 r0 bottom
R35 "0ohm" RES/0603 2470,2271 r180 bottom
R36 "NS" RES/0603 1339,2488 r270 bottom
R37 "NS" RES/0603 1482,2399 r270 bottom
R38 "0" RES/0603 1280,2315 r0 bottom
R39 "0" RES/0603 1280,2370 r0 bottom
R40 "0" RES/0603 1805,2230 r180 bottom
R41 "0" RES/0603 1449,2228 r180 bottom
R42 "NS" RES/0603 1235.5,1112 r270 bottom
R43 "10m" RES/0805 1286,1345 r270 top
R44 "75k" RES/0603 1107.5,1041 r270 bottom
R45 "NS" RES/0603 1244.5,917 r90 bottom
R46 "34.8" RES/0603 1098.5,924 r0 bottom
R47 "NS" RES/0603 2724,1112 r270 bottom
R48 "10m" RES/0805 2770,1345 r270 top
R49 "102k" RES/0603 2595.67,1041 r270 bottom
R50 "NS" RES/0603 2732.67,917 r90 bottom
R51 "82k" RES/0603 2586.67,924 r0 bottom
R52 "100k/RES0603" RES/0603 1979.58,1052 r90 bottom
R53 "10m" RES/0805 2028,1345 r270 top
R54 "158k" RES/0603 1851.58,981 r90 bottom
R55 "100k/RES0603" RES/0603 1988.58,977 r270 bottom
R56 "422k" RES/0603 1902.58,924 r180 bottom
R57 "100k/RES0603" RES/0603 5700,1052 r90 bottom
R58 "10m" RES/0805 5738,1345 r270 top
R59 "62k/RES0603" RES/0603 5572,981 r90 bottom
R60 "100k/RES0603" RES/0603 5709,977 r270 bottom
R61 "953k/RES0603" RES/0603 5623,924 r180 bottom
R62 "NS" RES/0603 4955.92,1112 r270 bottom
R63 "10m" RES/0805 4996,1345 r270 top
R64 "102k" RES/0603 4827.92,1041 r270 bottom
R65 "NS" RES/0603 4964.92,917 r90 bottom
R66 "82k" RES/0603 4818.92,924 r0 bottom
R67 "NS" RES/0603 3467.75,1112 r270 bottom
R68 "10m" RES/0805 3512,1345 r270 top
R69 "158k" RES/0603 3339.75,1041 r270 bottom
R70 "NS" RES/0603 3476.75,917 r90 bottom
R71 "180k" RES/0603 3330.75,924 r0 bottom
R72 "10m" RES/0805 4254,1345 r270 top
R73 "100k" RES0603 4211.83,1052 r90 bottom
R74 "102k" RES0603 4081,977 r90 bottom
R75 "100k" RES0603 4220.83,977 r270 bottom
R76 "82k" RES0603 4134.83,924 r180 bottom
R77 "10k" RES/0603 5475,2331 r270 bottom
R78 "10m/RES2512" RES2512 5595,1782 r90 top
R79 "4.53/RES0603" RES0603 5919,2364 r180 bottom
R80 "0" RES/0603 5593,3099 r90 bottom
R81 "100k/RES0603" RES/0603 5347,2344 r90 bottom
R82 "10k" RES/0603 5422,2369 r90 bottom
R83 "100k/RES0603" RES/0603 5344,2291 r180 bottom
R84 "2k" RES/0603 5795,2303 r90 bottom
R85 "0" RES/0603 5533,3099 r90 bottom
R86 "15k" RES/0603 5755,2213 r180 bottom
R87 "100k/RES0603" RES/0603 6204.5,2190.83 r270 bottom
R88 "102k/RES0603" RES0603 6339,2265 r270 bottom
R89 "100k/RES0603" RES/0603 6195.5,2265.83 r90 bottom
R90 "806k/RES0603" RES0603 6281.5,2318.83 r0 bottom
R91 "10k" RES/0603 3731,2259 r90 bottom
R92 "10m/RES2512" RES2512 3934,1782 r90 top
R93 "1k" RES/0603 4237,2380 r180 bottom
R94 "0" RES/0603 3852,3252 r90 bottom
R95 "10k" RES/0603 3546,2370 r90 bottom
R96 "10k" RES/0603 3601,2397 r90 bottom
R97 "10k" RES/0603 3675,2399 r270 bottom
R98 "1k" RES/0603 4125,2379 r270 bottom
R99 "0" RES/0603 3903,3252 r90 bottom
R100 "4.99k" RES0603 3995,2229 r0 bottom
R101 "100k" RES/0603 4457.5,2190.83 r270 bottom
R102 "158k" RES0603 4531,2221 r270 bottom
R103 "100k" RES/0603 4448.5,2265.83 r90 bottom
R104 "51k" RES0603 4592,2279 r180 bottom
R105 "316k" RES0603 4527,2341 r0 bottom
RL1 "100" RES/0805 1917,3633 r0 bottom
RL2 "100" RES/0805 4235,376 r180 bottom
RL3 "100" RES/0805 3832,3613 r0 bottom
RL4 "100" RES/0805 1999,358 r180 bottom
RL5 "100" RES/0805 5719,382 r180 bottom
RL6 "100" RES/0805 5723,3624 r180 bottom
RL7 "100" RES/0805 4977,383 r180 bottom
RL8 "100" RES/0805 1251,364 r180 bottom
RL9 "100" RES/0805 2741,359 r180 bottom
RL10 "100" RES/0805 3485,361 r180 bottom
TSEL "SWITCH_SPDT_WE" JUMPER/3PIN-WE450301014042 288,2642 r270 top (schematic designator SW2)
U1 "SLG46120" SLG4MP41885 523,2816 r90 bottom
U2 "MPM3695-25" "MPM3695-25 - ROY" 2583,2492 r180 top
U3 "MPM3695-25" "MPM3695-25 - ROY" 1609,2492 r180 top
U4 "MPM3630A" QFN20-3X5MM 1282,895 r0 top
U5 "MPM3630A" QFN20-3X5MM 2770.17,895 r0 top
U6 "MPM3630A" QFN20-3X5MM 2026.08,895 r0 top
U7 "MPM3630A" QFN20-3X5MM 5746.5,895 r0 top
U8 "MPM3630A" QFN20-3X5MM 5002.42,895 r0 top
U9 "MPM3630A" QFN20-3X5MM 3514.25,895 r0 top
U10 "MPM3630A" QFN20-3X5MM 4258.33,895 r0 top
U11 "MPM3695-10" QFN45-MPM3695-10 5567,2420.4 r180 top
U12 "MPM3630A" QFN20-3X5MM 6158,2347.83 r180 top
U13 "MPM3695-25" "MPM3695-25 - ROY" 3858,2492 r180 top
U14 "MPM3630A" QFN20-3X5MM 4411,2347.83 r180 top
UAUX1 "MPM3630A" QFN20-3X5MM 608.31,2363 r0 bottom
VIN "VIN" BANANA-K575 348,1709 r0 top (schematic designator CN3)
VOUT_R1 "VOUT_R1" KEYSTONE-7697-75 1468,3484 r0 top (schematic designator CN1)
VOUT_R2 "TP2MM" TP2MM 4322.67,159 r0 top (schematic designator CN17)
VOUT_R3 "VOUT_R3" BANANA-K575 3559,3427 r0 top (schematic designator CN21)
VOUT_R4 "TP2MM" TP2MM 2102.17,159 r0 top (schematic designator CN9)
VOUT_R5 "TP2MM" TP2MM 5803,159 r0 top (schematic designator CN11)
VOUT_R6 "VOUT_R6" BANANA-K575 6001.17,3427 r0 top (schematic designator CN19)
VOUT_R7 "TP2MM" TP2MM 5062.83,159 r0 top (schematic designator CN13)
VOUT_R8 "TP2MM" TP2MM 1362,159 r0 top (schematic designator CN5)
VOUT_R9 "TP2MM" TP2MM 2842.33,159 r0 top (schematic designator CN7)
VOUT_R10 "TP2MM" TP2MM 3582.5,159 r0 top (schematic designator CN15)

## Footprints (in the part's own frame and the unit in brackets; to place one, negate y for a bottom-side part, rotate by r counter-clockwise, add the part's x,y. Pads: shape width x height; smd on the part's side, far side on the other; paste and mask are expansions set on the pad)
BANANA-K575 [mil]
  round 415 hole 210: 1(0,0)
  round 28 hole 16: 2(-114.1,114.06) 3(0,150) 4(114.06,114.06) 5(150,0) 6(114.06,-114.06) 7(0,-150) 8(-114.06,-114.1) 9(-150,0)
  silkscreen extent -210,-210 210,210
CAP0402 [mil]
  rect 20x22 smd paste-2 mask+2: 1(0,0) 2(35,0)
  silkscreen extent -13,-15 48,15, body extent 0,-10 35,10, height 22
CAP0603 [mil]
  rect 30x35 smd paste-2 mask+2: 1(0,0) 2(50,0)
  silkscreen extent -20,-25 70,25, body extent -5,-15 55,15, height 20
CAP0805 [mil]
  rect 45x50 smd paste-2 mask+2: 1(0,0) 2(70,0)
  silkscreen extent -25,-30 95,30, body extent -20,-25 90,25, height 50
CAP/0603 [mil]
  rect 30x35 smd paste-2 mask+2: 1(0,0) 2(60,0)
  silkscreen extent -20,-20 80,20, body extent -5,-15 65,15, height 32
CAP/1210 [mm]
  rect 1.5x2.3 smd paste+0 mask+0.051: 1(0,0) 2(3.048,0)
  silkscreen extent -1.02,-1.4 4.06,1.4
CAP/OD8.0P3.5 [mm]
  rect 2x2 hole 1: 1(0,0)
  round 2 hole 1: 2(3.556,0)
  silkscreen extent -3.94,-4.06 5.84,4.06
HDR2X5 [mm] "Connector; Header; 5x2 Position"
  rect 1.5x1.5 hole 0.9: 1(0,0)
  round 1.5 hole 0.9: 2(0,2.54) 3(2.54,0) 4(2.54,2.54) 5(5.08,0) 6(5.08,2.54) 7(7.62,0) 8(7.62,2.54) 9(10.16,0) 10(10.16,2.54)
  silkscreen extent -1.27,-1.27 11.43,3.81
JUMPER/3PIN-WE450301014042 [mil]
  rect 62x62 hole 38 mask+2: 1(0,0)
  round 62 hole 38 mask+2: 2(100,0) 3(200,0)
  silkscreen extent -100,-50 300,50
KEYSTONE-7697-75 [mil]
  round 120 hole 75: 1(98.43,-137.8) 2(-98.43,-137.8) 3(98.43,137.8) 4(-98.43,137.8)
  silkscreen extent -158,-175 158,175
LED/SMD/0805 [mm]
  rect 1x1 smd paste-25.4: 1(0,0) 2(2.032,0)
  silkscreen extent -0.74,-0.66 2.67,0.64
"MPM3695-25 - ROY" [mm]
  rect 1.55x0.3 smd mask+0.051: 1(-4.525,4.55) 2(-4.525,3.9) 3(-4.525,3.25) 4(-4.525,2.6) 5(-4.525,1.95) 6(-4.525,1.3) 7(-4.525,0.65) 8(-4.525,0) 9(-4.525,-0.65) 10(-4.525,-1.3) 11(-4.525,-1.95) 12(-4.525,-2.6) 13(-4.525,-3.25) 14(-4.525,-4.55) 25(4.525,-4.55) 26(4.525,-3.25) 27(4.525,-2.6) 28(4.525,-1.95) 29(4.525,-1.3) 31(4.525,0) 32(4.525,0.65) 33(4.525,1.3) 34(4.525,1.95) 35(4.525,2.6) 36(4.525,3.25) 37(4.525,3.9) 38(4.525,4.55)
  rect 0.95x1.3 smd mask+0.051: 1(-4.225,5.05) 39(4.225,5.05)
  rect 2.9x1.6 smd mask+0.051: 11(-3.25,-2.6) 28(3.25,-2.6)
  rect 2.9x1.3 smd mask+0.051: 14(-3.25,-5.05) 25(3.25,-5.05)
  rect 0.3x1.55 smd mask+0.051: 15(-3.9,-5.525) 16(-3.25,-5.525) 17(-2.6,-5.525) 18(-1.95,-5.525) 19(-0.65,-5.525) 20(0.65,-5.525) 21(1.95,-5.525) 22(2.6,-5.525) 23(3.25,-5.525) 24(3.9,-5.525) 39(3.9,5.525) 40(3.25,5.525) 41(2.6,5.525) 42(1.95,5.525) 43(1.3,5.525) 44(0.65,5.525) 45(-0.65,5.525) 46(-1.3,5.525) 47(-1.95,5.525) 48(-2.6,5.525) 49(-3.25,5.525)
  rect 1.6x3.9 smd mask+0.051: 19(0,-3.75)
  rect 1.2x1 smd mask+0.051: 30(2.4,-0.3)
  rect 0.5x0.5 smd mask+0.051: 30(3.2,-0.55)
  rect 0.381x0.965 smd rot 45 mask+0.051: 30(3.201,-0.299)
  rect 1.95x0.3 smd mask+0.051: 30(4.325,-0.65)
  rect 0.95x2.7 smd mask+0.051: 43(0.975,4.244) 45(-0.975,4.252)
  rect 0.3x1.5 smd mask+0.051: 50(-3.9,5.556)
  rect 1.6x1.8 smd mask+0.051: 51(0,1.1)
  Top Layer pour cut-out: 2.33,4.049 2.33,0.747 3.131,0.747 3.131,4.049
  Top Layer pour cut-out: -2.932,4.049 -2.932,0.747 -2.132,0.747 -2.132,4.049
  silkscreen extent -6.5,-6.73 5.83,6.5
POSCAP/D2 [mm]
  rect 2.5x4.3 smd paste-25.4 mask+0.051: 1(0,0) 2(5.699,0)
  silkscreen extent -1.78,-2.29 6.98,2.29, body extent -0.64,-2.16 6.35,2.16, height 2.03
QFN20-3X5MM [mm]
  rect 0.7x0.25 smd: 1(-1.45,1.55) 4(-1.45,-0.4) 5(-1.45,-1.25) 6(-1.45,-2.1) 7(1.45,-2.1) 8(1.45,-1.25) 9(1.45,-0.4) 12(1.45,1.55)
  rect 1.1x0.25 smd: 2(-1.25,0.9) 3(-1.25,0.25) 10(1.25,0.25) 11(1.25,0.9)
  rect 0.6x1.95 smd: 5(-1,-1.25) 8(1,-1.25)
  rect 0.25x0.7 smd: 13(1.25,2.45) 14(0.75,2.45) 17(-0.75,2.45) 18(-1.25,2.45)
  rect 0.25x1.1 smd: 15(0.25,2.25) 16(-0.25,2.25)
  silkscreen extent -2.7,-2.5 1.5,2.5
QFN45-MPM3695-10 [mm]
  rect 1.05x0.25 smd mask+0.051: 1(-3.775,3.25) 2(-3.775,2.6) 3(-3.775,1.95) 4(-3.775,1.3) 5(-3.775,0.65) 6(-3.775,0) 7(-3.775,-0.65) 8(-3.775,-1.3) 9(-3.775,-1.95) 10(-3.775,-2.6) 11(-3.775,-3.25) 23(3.775,-3.25) 24(3.775,-2.6) 25(3.775,-1.95) 26(3.775,-1.3) 27(3.775,-0.65) 28(3.775,0) 29(3.775,0.65) 30(3.775,1.3) 31(3.775,1.95) 32(3.775,2.6) 33(3.775,3.25)
  rect 0.3x0.4 smd rot 135.1 mask+0.051: 1(-3.461,3.407)
  rect 2.025x1.875 smd mask+0.051: 9(-2.688,-2.762) 19(2.688,-2.762)
  rect 0.25x1.175 smd mask+0.051: 12(-3.3,-3.712) 34(3.3,3.712) 45(-3.3,3.712)
  rect 0.25x1.05 smd mask+0.051: 13(-2.8,-3.775) 14(-2.3,-3.775) 15(-1.8,-3.775) 16(-0.65,-3.775) 17(0,-3.775) 18(0.65,-3.775) 19(1.8,-3.775) 20(2.3,-3.775) 21(2.8,-3.775) 22(3.3,-3.775) 35(2.8,3.775) 36(2.3,3.775) 37(1.8,3.775) 38(1.3,3.775) 39(0.65,3.775) 40(-0.65,3.775) 41(-1.3,3.775) 42(-1.8,3.775) 43(-2.3,3.775) 44(-2.8,3.775)
  rect 1.55x4.2 smd mask+0.051: 16(0,-1.6)
  rect 0.525x0.575 smd mask+0.051: 33(3.437,3.413)
  rect 0.9x2 smd mask+0.051: 38(0.975,2.7) 40(-0.975,2.7)
  Top Layer pour cut-out: -3.175,2.794 -3.175,-0.889 -2.032,-0.889 -2.032,3.175 -2.794,3.175
  Top Layer pour cut-out: 1.991,3.175 1.991,-1.524 3.175,-1.524 3.175,2.794 2.794,3.175
  silkscreen extent -5.73,-4.51 4.52,4.51
RES0603 [mil]
  rect 35x35 smd paste-1000: 1(0,0) 2(65,0)
  silkscreen extent -20,-20 85,20
RES2512 [mil]
  rect 60x130 smd paste-1000 mask+2: 1(0,0) 2(230,0)
  silkscreen extent -40,-75 270,75
RES/0603 [mil]
  rect 31.5x31.5 smd paste-1000: 1(0,0) 2(60,0)
  silkscreen extent -20,-20 80,20
RES/0805 [mil]
  rect 45x50 smd paste-1000: 1(0,0) 2(85,0)
  silkscreen extent -25,-30 110,30
SLG4MP41885 [mm]
  round 0.5 on Bottom Overlay mask+0.051: 0(-1.143,1.016)
  oval 0.465x0.2 smd mask+0.051: 1(-0.717,0.6)
  rect 0.465x0.2 smd mask+0.051: 2(-0.717,0.2) 3(-0.717,-0.2) 4(-0.717,-0.6) 7(0.717,-0.6) 8(0.717,-0.2) 9(0.717,0.2) 10(0.717,0.6)
  rect 0.2x0.39 smd mask+0.051: 5(-0.2,-0.775) 6(0.2,-0.775)
  rect 0.2x0.4 smd mask+0.051: 11(0.2,0.775) 12(-0.2,0.775)
  silkscreen extent -0.89,-0.89 0.89,0.89
TP2MM [mil]
  round 189 hole 82.7: 1(0,0)
  silkscreen extent -112,-112 112,112
ZVN3320/SOT23 [mm]
  rect 1x1 smd paste-25.4: 1(-1.016,-1.143) 2(1.016,-1.143) 3(0,1.016)
  silkscreen extent -1.52,-0.38 1.52,0.51

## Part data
C1 C2 C3 C4 C7 C8 C9 C10 C14 C15 C16 C17 C18 C19 C20 C21 C22 C23 C24 C25 C26 C27 C28 C29 C30 C31 C32 C33 C34 C35 C36 C37 C38 C39 C40 C41 C42 C43 C44 C46 C49 C50 C51 C52 C53 C54 C55 C56 C57 C58 C59 C60 C61 C62 C63 C64 C65 C66 C67 C68 C73 C76 C77 C78 C79 C80 C81 C82 C83 C84 C85 C86 C87 C88 C89 C90 C91 C92 C93 C94 C95 C98 C99 C100 C101 C102 C103 C104 C105 C106 C107 C108 C109 C110 C111 C112 C113 C115 C119 C120 C121: library part Cap, "Capacitor"
C5 C6 C69 C74 C75 C96 C97 CN18 EN GND GND GND GND GND GND Q1 Q2 Q3 Q4 R23 R24 TSEL VOUT_R2 VOUT_R4 VOUT_R5 VOUT_R7 VOUT_R8 VOUT_R9 VOUT_R10: "{Description}"
C11: library part CAP0603, "{Description}"
C12 C13: library part CAP/OD8.0P3.5, "{Description}"
C45 C47 C48 C114 C116 C117 C118: "Capacitor"
C70 C71 C72: library part CAP0805, "{Description}"
D1 D2 D3 D4: library part 19.0004, "LED;绿光"
GND VOUT_R1: library part KEYSTONE7697-75, "{Description}"
GND GND GND VIN VOUT_R3 VOUT_R6: library part BANANA-K575, "Connector, RCA Jack, R/A"
PMBus1: "Header, 5-Pin, Dual row"
R1 R2 R3 R6 R8 R22 R25 R26 R27 R28 R29 R30 R31 R32 R33 R34 R35 R36 R37 R38 R39 R40 R41 R42 R43 R44 R45 R46 R47 R48 R49 R50 R51 R52 R53 R54 R55 R56 R57 R58 R59 R60 R61 R62 R63 R64 R65 R66 R67 R68 R69 R70 R71 R72 R73 R74 R75 R76 R77 R79 R80 R81 R82 R83 R84 R85 R86 R87 R88 R89 R90 R91 R93 R94 R95 R96 R97 R98 R99 R100 R101 R102 R103 R104 R105: library part Res1, "Resistor"
R4 R5 R18 R19 R20 R21: library part Res3, "Resistor"
R9 R10 R11 R12 R13 R14 R15 R16 R17 R78 R92 RL1 RL2 RL3 RL4 RL5 RL6 RL7 RL8 RL9 RL10: library part RES2512, "{Description}"
U1: "GreenPAK Programmable Mixed Signal Array"
U4 U5 U6 U7 U8 U9 U10 U12 U14 UAUX1: "18V/3A DC/DC Module Synchronous Step-Down Regulator"

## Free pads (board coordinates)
  round 78.74 hole 39.37 mask+2: 0(75,2954)

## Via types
v1: diameter 15.75, hole 7.87, Top Layer to Bottom Layer, tented both sides, 1280 vias
v2: diameter 19.68, hole 11.81, Top Layer to Bottom Layer, tented both sides, 10 vias

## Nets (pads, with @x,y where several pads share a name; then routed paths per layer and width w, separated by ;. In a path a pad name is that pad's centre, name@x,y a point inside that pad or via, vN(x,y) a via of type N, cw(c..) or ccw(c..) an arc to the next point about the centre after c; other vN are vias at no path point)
ALT: pad.0 R30.2 R82.1 R96.1 U2.35 U3.35 U11.30 U13.35 | length 13355.5
  Top Layer w10: v1(1385.18,2389.64) U3.35@1430.85,2389.64 ; v1(2359.18,2389.64) U2.35@2404.85,2389.64 ; v1(3634.18,2389.64) U13.35@3679.85,2389.64 ; v1(5386.4,2369.22) U11.30@5418.38,2369.22
  Mid-Layer 2 w8: pad.0@75,2954 75,2997 252,3174 1624.37,3174 1673.37,3125 2112.63,3125 2140.63,3153 5053.37,3153 5260.06,2946.31 5260.06,2407.31 5293.37,2374 5367.08,2374 5371.86,2369.22 v1(5386.4,2369.22) 5416.78,2369.22 5439,2347 5439,2308 5417,2286 5212,2286 4577.06,2920.94 3626.94,2920.94 3443.06,2737.06 3443.06,2449.94 3499,2394 3615.28,2394 3619.64,2389.64 v1(3634.18,2389.64) 3658.73,2389.64 3681,2367.37 3681,2314.25 3295.75,1929 1444,1929 1364,2009 1364,2383 1370.64,2389.64 v1(1385.18,2389.64) 1396.64,2389.64 1415.82,2408.82 1753.55,2408.82 1799.47,2362.9 2308.9,2362.9 2335.64,2389.64 v1(2359.18,2389.64)
  Bottom Layer w8: v1(1385.18,2389.64) R30.2@1422.64,2389.64 ; R96.1@3601,2397 3608.36,2389.64 v1(3634.18,2389.64)
  Bottom Layer w10: v1(5386.4,2369.22) 5421.78,2369.22 R82.1@5422,2369
AUX_3V3: C2.2 C3.2 C4.2 D1.2 D2.2 D3.2 D4.2 R3.2 R4.2 R5.2 R32.1 R33.2 U1.1 UAUX1.7 UAUX1.8 UAUX1.9 | length 1730.5
  Top Layer w20: D1.2@136,3432 139,3429 v2(632,3429)
  Bottom Layer w8: U1.1@546.62,2787.75 546.62,2716.38 C4.2@556,2707
  Bottom Layer w20: R33.2@347,3403 R32.1@550,3403 606,3403 v2(632,3429) ; R3.2@378,2359 378,2589 432,2643 638,2643 659,2622 C3.2@659,2586 ; R4.2@428,3072 610,3072 v2(633.56,3048.44) R5.2@633.56,2989
  other v1: 705.5,2496.5 731,2496.5 705.5,2522 731,2522 705.5,2547.5 731,2547.5
EN_SEQ: EN.2 R4.1 R14.1 | length 771.4
  Mid-Layer 4 w10: EN.2@164,2542 107,2542 70,2579 70,2740.67 v1(366.33,3037)
  Bottom Layer w10: R14.1@366.33,2989 v1(366.33,3037) R4.1@366.33,3070.33
GND: C1.1 C2.1 C3.1 C4.1 C5.2 C6.2 C7.1 C8.1 C9.1 C10.1 C12.2 C13.2 C14.1 C15.1 C16.1 C17.1 C18.1 C19.1 C20.1 C21.1 C22.1 C23.1 C24.1 C25.1 C26.1 C27.1 C28.1 C29.1 C30.1 C31.1 C32.1 C33.1 C34.1 C35.1 C36.1 C38.1 C39.1 C40.1 C41.1 C42.1 C44.1 C45.1 C46.1 C47.1 C48.1 C50.1 C51.1 C52.1 C53.1 C54.1 C56.1 C57.1 C58.1 C59.1 C60.1 C62.1 C63.1 C64.1 C65.1 C66.1 C68.1 C69.1 C70.1 C71.1 C72.1 C74.2 C75.2 C76.1 C77.1 C79.1 C80.1 C81.1 C82.1 C83.1 C84.1 C85.1 C86.1 C87.1 C88.1 C89.1 C90.1 C91.1 C92.1 C93.1 C94.1 C96.2 C97.2 C98.1 C99.1 C100.1 C101.1 C102.1 C103.1 C104.1 C105.1 C107.1 C108.1 C109.1 C110.1 C111.1 C112.1 C113.1 C114.1 C115.1 C116.1 C117.1 C118.1 C120.1 C121.1 CN18.1 EN.1 GND.1 GND.2 GND.3 GND.4 GND.5 GND.6 GND.7 GND.8 GND.9 PMBus1.3 PMBus1.4 PMBus1.7 PMBus1.8 Q1.2 Q2.2 Q3.2 Q4.2 R8.1 R28.2 R34.2 R40.1 R46.2 R51.2 R56.1 R61.1 R66.2 R71.2 R76.1 R85.1 R86.1 R90.1 R99.1 R100.2 R105.1 RL1.2 RL2.2 RL3.2 RL4.2 RL5.2 RL6.2 RL7.2 RL8.2 RL9.2 RL10.2 TSEL.1 U1.7 U2.1 U2.5 U2.14 U2.15 U2.16 U2.17 U2.18 U2.19 U2.20 U2.21 U2.22 U2.23 U2.24 U2.25 U2.30 U2.43 U2.44 U2.50 U3.1 U3.5 U3.14 U3.15 U3.16 U3.17 U3.18 U3.19 U3.20 U3.21 U3.22 U3.23 U3.24 U3.25 U3.30 U3.43 U3.44 U3.50 U4.3 U4.12 U4.13 U4.14 U5.3 U5.12 U5.13 U5.14 U6.3 U6.12 U6.13 U6.14 U7.3 U7.12 U7.13 U7.14 U8.3 U8.12 U8.13 U8.14 U9.3 U9.12 U9.13 U9.14 U10.3 U10.12 U10.13 U10.14 U11.1 U11.5 U11.19 U11.20 U11.21 U11.22 U11.23 U11.24 U11.25 U11.38 U11.39 U11.45 U12.3 U12.12 U12.13 U12.14 U13.1 U13.5 U13.14 U13.15 U13.16 U13.17 U13.18 U13.19 U13.20 U13.21 U13.22 U13.23 U13.24 U13.25 U13.30 U13.43 U13.44 U13.50 U14.3 U14.12 U14.13 U14.14 UAUX1.3 UAUX1.12 UAUX1.13 UAUX1.14 | length 1765.5
  Top Layer w10: v1(1158.5,897) 1185.5,897 1193.34,904.84 U4.3@1232.79,904.84 ; C21.1@1318.64,2711.36 C22.1@1318.64,2777 ; C22.1@1318.64,2811.36 C22.1@1318.64,2777 ; C22.1@1337.64,2796 C22.1@1318.64,2777 ; U3.5@1787.15,2415.23 v1(1849,2415.23) ; v1(1902.58,897) 1929.58,897 1937.43,904.84 U6.3@1976.87,904.84 ; C7.1@2289,2715 C8.1@2289,2777 ; C8.1@2289,2815 C8.1@2289,2777 ; C8.1@2308,2796 C8.1@2289,2777 ; v1(2646.67,897) 2673.67,897 2681.51,904.84 U5.3@2720.95,904.84 ; U2.5@2761.15,2415.23 v1(2829,2415.23) ; v1(3390.75,897) 3417.75,897 3425.59,904.84 U9.3@3465.04,904.84 ; U13.5@4036.15,2415.23 v1(4106,2415.23) ; v1(4134.83,897) 4161.83,897 4169.68,904.84 U10.3@4209.12,904.84 ; U14.3@4460.21,2337.99 4496.99,2337.99 v1(4501,2342) ; v1(4878.92,897) 4905.92,897 4913.76,904.84 U8.3@4953.2,904.84 ; v1(5623,897) 5650,897 5657.84,904.84 U7.3@5697.29,904.84 ; U11.5@5715.62,2394.81 v1(5747.6,2394.81) ; U12.3@6207.21,2337.99 6246.66,2337.99 6254.5,2345.83 v1(6281.5,2345.83)
  Bottom Layer w10: v1(1158.5,897) R46.2@1158.5,924 ; v1(1902.58,897) R56.1@1902.58,924 ; R28.2@2007,3131 2029.73,3153.73 v1(2029.73,3190.14) ; v1(2646.67,897) R51.2@2646.67,924 ; v1(3390.75,897) R71.2@3390.75,924 ; R99.1@3903,3252 3988.37,3166.63 C97.2@3988.37,3118 ; v1(4134.83,897) R76.1@4134.83,924 ; v1(4878.92,897) R66.2@4878.92,924 ; C75.2@5444.63,2972 5444.63,3010.63 R85.1@5533,3099 ; v1(5623,897) R61.1@5623,924 ; R90.1@6281.5,2318.83 v1(6281.5,2345.83)
  other v1: 1622,348.5 1728.75,348.5 1835.5,348.5 2371,351.5 2477.75,351.5 2584.5,351.5 3114,351.5 3220.75,351.5 3327.5,351.5 3860,351.5 3966.75,351.5 4073.5,351.5 4588,356.5 4694.75,356.5 4801.5,356.5 5280.5,356.5 5348,356.5 5454.75,356.5 648,359.5 754.75,359.5 861.5,359.5 1622,455.25 1728.75,455.25 1835.5,455.25 2371,458.25 2477.75,458.25 2584.5,458.25 3114,458.25 3220.75,458.25 3327.5,458.25 3860,458.25 3966.75,458.25 4073.5,458.25 4588,463.25 4694.75,463.25 4801.5,463.25 5280.5,463.25 5348,463.25 5454.75,463.25 648,466.25 754.75,466.25 861.5,466.25 1622,562 1728.75,562 1835.5,562 2371,565 2477.75,565 2584.5,565 3114,565 3220.75,565 3327.5,565 3860,565 3966.75,565 4073.5,565 4588,570 4694.75,570 4801.5,570 5280.5,570 5348,570 5454.75,570 648,573 754.75,573 861.5,573 1167,643.5 1192.5,643.5 1218,643.5 1911.08,643.5 1936.58,643.5 1962.08,643.5 2655.17,643.5 2680.67,643.5 2706.17,643.5 3399.25,643.5 3424.75,643.5 3450.25,643.5 4143.33,643.5 4168.83,643.5 4194.33,643.5 4887.42,643.5 4912.92,643.5 4938.42,643.5 5631.5,643.5 5657,643.5 5682.5,643.5 1167,669 1192.5,669 1218,669 1911.08,669 1936.58,669 1962.08,669 2655.17,669 2680.67,669 2706.17,669 3399.25,669 3424.75,669 3450.25,669 4143.33,669 4168.83,669 4194.33,669 4887.42,669 4912.92,669 4938.42,669 5631.5,669 5657,669 5682.5,669 1167,694.5 1192.5,694.5 1218,694.5 1911.08,694.5 1936.58,694.5 1962.08,694.5 2655.17,694.5 2680.67,694.5 2706.17,694.5 3399.25,694.5 3424.75,694.5 3450.25,694.5 4143.33,694.5 4168.83,694.5 4194.33,694.5 4887.42,694.5 4912.92,694.5 4938.42,694.5 5631.5,694.5 5657,694.5 5682.5,694.5 6162,706.5 6268.75,706.5 6375.5,706.5 1167,721.5 1192.5,721.5 1218,721.5 1911.08,721.5 1936.58,721.5 1962.08,721.5 2655.17,721.5 2680.67,721.5 2706.17,721.5 3399.25,721.5 3424.75,721.5 3450.25,721.5 4143.33,721.5 4168.83,721.5 4194.33,721.5 4887.42,721.5 4912.92,721.5 4938.42,721.5 5631.5,721.5 5657,721.5 5682.5,721.5 1167,747 1192.5,747 1218,747 1911.08,747 1936.58,747 1962.08,747 2655.17,747 2680.67,747 2706.17,747 3399.25,747 3424.75,747 3450.25,747 4143.33,747 4168.83,747 4194.33,747 4887.42,747 4912.92,747 4938.42,747 5631.5,747 5657,747 5682.5,747 1167,772.5 1192.5,772.5 1218,772.5 1911.08,772.5 1936.58,772.5 1962.08,772.5 2655.17,772.5 2680.67,772.5 2706.17,772.5 3399.25,772.5 3424.75,772.5 3450.25,772.5 4143.33,772.5 4168.83,772.5 4194.33,772.5 4887.42,772.5 4912.92,772.5 4938.42,772.5 5631.5,772.5 5657,772.5 5682.5,772.5 6162,813.25 6268.75,813.25 6375.5,813.25 6162,920 6268.75,920 6375.5,920 1355,973.5 1380.5,973.5 1406,973.5 1433,973.5 2099.08,973.5 2124.58,973.5 2150.08,973.5 2177.08,973.5 2843.17,973.5 2868.67,973.5 2894.17,973.5 2921.17,973.5 3587.25,973.5 3612.75,973.5 3638.25,973.5 3665.25,973.5 4331.33,973.5 4356.83,973.5 4382.33,973.5 4409.33,973.5 5075.42,973.5 5100.92,973.5 5126.42,973.5 5153.42,973.5 5819.5,973.5 5845,973.5 5870.5,973.5 5897.5,973.5 1355,999 1380.5,999 1406,999 1433,999 2099.08,999 2124.58,999 2150.08,999 2177.08,999 2843.17,999 2868.67,999 2894.17,999 2921.17,999 3587.25,999 3612.75,999 3638.25,999 3665.25,999 4331.33,999 4356.83,999 4382.33,999 4409.33,999 5075.42,999 5100.92,999 5126.42,999 5153.42,999 5819.5,999 5845,999 5870.5,999 5897.5,999 1355,1024.5 1380.5,1024.5 1406,1024.5 1433,1024.5 2099.08,1024.5 2124.58,1024.5 2150.08,1024.5 2177.08,1024.5 2843.17,1024.5 2868.67,1024.5 2894.17,1024.5 2921.17,1024.5 3587.25,1024.5 3612.75,1024.5 3638.25,1024.5 3665.25,1024.5 4331.33,1024.5 4356.83,1024.5 4382.33,1024.5 4409.33,1024.5 5075.42,1024.5 5100.92,1024.5 5126.42,1024.5 5153.42,1024.5 5819.5,1024.5 5845,1024.5 5870.5,1024.5 5897.5,1024.5 3042,1961.75 3148.75,1961.75 3255.5,1961.75 5425,2045 5450.5,2045 5476,2045 3042,2068.5 3148.75,2068.5 3255.5,2068.5 3362.25,2068.5 5425,2070.5 5450.5,2070.5 5476,2070.5 5425,2096 5450.5,2096 5476,2096 1514,2097 1586,2097 2488,2097 2560,2097 3763,2097 3835,2097 1933,2110 2039,2110 2186,2112 1514,2133.5 1586,2133.5 2488,2133.5 2560,2133.5 3763,2133.5 3835,2133.5 4272,2161 4298,2161 1932,2169 1514,2170 1586,2170 2488,2170 2560,2170 3763,2170 3835,2170 2041,2171 3042,2175.25 3148.75,2175.25 3255.5,2175.25 3362.25,2175.25 3469,2175.25 2186,2176 5522,2190 5486,2191 4272,2200 4298,2200 5487,2216 5522,2216 6011,2216 6036.5,2216 6062,2216 686.5,2234.5 712,2234.5 737.5,2234.5 6011,2241.5 6036.5,2241.5 6062,2241.5 1595,2246.3 2569,2246.3 3844,2246.3 1801,2252.5 1847.5,2252.5 2775,2252.5 2821.5,2252.5 4050,2252.5 4096.5,2252.5 5550,2254 686.5,2260 712,2260 737.5,2260 5754,2264 5529,2265 6011,2267 6036.5,2267 6062,2267 1595,2279.63 2569,2279.63 3844,2279.63 3042,2282 3148.75,2282 3255.5,2282 3362.25,2282 3469,2282 686.5,2285.5 712,2285.5 737.5,2285.5 4088,2288 5550,2289 5753,2291 2808,2298 1801,2299 1847.5,2299 2775,2299 4050,2299 1595,2312.97 2569,2312.97 3844,2312.97 5550,2320 1595,2346.3 2569,2346.3 3844,2346.3 4705.75,2366.5 4812.5,2366.5 4919.25,2366.5 5528,2369 493,2377 3819,2383 1576,2384 2546,2386 4705.75,2473.25 4812.5,2473.25 6211.5,2490 6237,2490 5374,2508 5412,2510 4463.5,2511 4489,2511 498.5,2512.5 524,2512.5 549.5,2512.5 6211.5,2515.5 6237,2515.5 5412,2536 4463.5,2536.5 4489,2536.5 498.5,2538 524,2538 549.5,2538 6211.5,2541 6237,2541 5374,2542 5337,2546 4463.5,2562 4489,2562 498.5,2563.5 524,2563.5 549.5,2563.5 5411,2565 5374,2576 4705.75,2580 1570,2589 1648,2589 2544,2589 2622,2589 3819,2589 3897,2589 5337,2593 5437,2598 5466,2599 5497,2600 5114.25,2602 1570,2623.75 1648,2623.75 2544,2623.75 2622,2623.75 3819,2623.75 3897,2623.75 5347,2624 5372.5,2624 5398,2624 5423.5,2624 5347,2649.5 5372.5,2649.5 5398,2649.5 5423.5,2649.5 1570,2658.5 1648,2658.5 2544,2658.5 2622,2658.5 3819,2658.5 3897,2658.5 6219.5,2661 6245,2661 4475.5,2669 4501,2669 5347,2675 5372.5,2675 5398,2675 5423.5,2675 5446,2675 5471.5,2675 5497,2675 1802,2684 2776,2684 4051,2684 1417,2685 2391,2685 3666,2685 434,2686 6219.5,2686.5 6245,2686.5 1570,2693.25 1648,2693.25 2544,2693.25 2622,2693.25 3819,2693.25 3897,2693.25 4475.5,2694.5 4501,2694.5 5368,2701 5393.5,2701 5419,2701 5446,2700.5 5471.5,2700.5 5497,2700.5 5007.5,2708.75 5114.25,2708.75 1417,2710 2391,2710 3666,2710 1801,2711 2775,2711 4050,2711 6219.5,2712 6245,2712 434,2720 4475.5,2720 4501,2720 5446,2726 5471.5,2726 5497,2726 5368,2726.5 5393.5,2726.5 5419,2726.5 1442,2728 1469,2728 1495,2728 1518,2728 1570,2728 1598,2728 1620,2728 1648,2728 1699,2728 1724,2728 1750,2728 1776,2728 2416,2728 2443,2728 2469,2728 2492,2728 2544,2728 2572,2728 2594,2728 2622,2728 2673,2728 2698,2728 2724,2728 2750,2728 3691,2728 3718,2728 3744,2728 3767,2728 3819,2728 3847,2728 3869,2728 3897,2728 3948,2728 3973,2728 3999,2728 4025,2728 5416,2769 5441.5,2769 5467,2769 5492.5,2769 6622.25,2771 1426,2773 1451.5,2773 1477,2773 1502.5,2773 1645,2773 1670.5,2773 1696,2773 1721.5,2773 1534,2775 1559.5,2775 1585,2775 1610.5,2775 3771,2778 3796.5,2778 3822,2778 3847.5,2778 3665,2779 3690.5,2779 3716,2779 3741.5,2779 3876,2779 3901.5,2779 3927,2779 3952.5,2779 2349,2791 2374.5,2791 2400,2791 2425.5,2791 2454,2792 2479.5,2792 2505,2792 2530.5,2792 2564,2792 2589.5,2792 2615,2792 2640.5,2792 5416,2794.5 5441.5,2794.5 5467,2794.5 5492.5,2794.5 4422,2798 4447.5,2798 1426,2798.5 1451.5,2798.5 1477,2798.5 1502.5,2798.5 1645,2798.5 1670.5,2798.5 1696,2798.5 1721.5,2798.5 1534,2800.5 1559.5,2800.5 1585,2800.5 1610.5,2800.5 3771,2803.5 3796.5,2803.5 3822,2803.5 3847.5,2803.5 3665,2804.5 3690.5,2804.5 3716,2804.5 3741.5,2804.5 3876,2804.5 3901.5,2804.5 3927,2804.5 3952.5,2804.5 4900.75,2815.5 5007.5,2815.5 5114.25,2815.5 2349,2816.5 2374.5,2816.5 2400,2816.5 2425.5,2816.5 2454,2817.5 2479.5,2817.5 2505,2817.5 2530.5,2817.5 2564,2817.5 2589.5,2817.5 2615,2817.5 2640.5,2817.5 5441.5,2820 5467,2820 5492.5,2820 1426,2824 1451.5,2824 1477,2824 1502.5,2824 1645,2824 1670.5,2824 1696,2824 1721.5,2824 4422,2823.5 4447.5,2823.5 1534,2826 1559.5,2826 1585,2826 1610.5,2826 3771,2829 3796.5,2829 3822,2829 3847.5,2829 3665,2830 3690.5,2830 3716,2830 3741.5,2830 3876,2830 3901.5,2830 3927,2830 3952.5,2830 2349,2842 2374.5,2842 2400,2842 2425.5,2842 2454,2843 2479.5,2843 2505,2843 2530.5,2843 2564,2843 2589.5,2843 2615,2843 2640.5,2843 459,2849 481,2849 4422,2849 4447.5,2849 446,2875 467,2876 6515.5,2877.75 6622.25,2877.75 3547,2915.14 6226.5,2930 6252,2930 3547,2940.64 5358.5,2946 5384,2946 6226.5,2955.5 6252,2955.5 3547,2966.14 5358.5,2971.5 5384,2971.5 6226.5,2981 6252,2981 6408.75,2984.5 6515.5,2984.5 6622.25,2984.5 5358.5,2997 5384,2997 3145.25,3008 4622,3008.75 4728.75,3008.75 4835.5,3008.75 3905,3044 3930.5,3044 3905,3069.5 3930.5,3069.5 3905,3095 3930.5,3095 3038.5,3114.75 3145.25,3114.75 4622,3115.5 4728.75,3115.5 4835.5,3115.5 4942.25,3115.5 2931.75,3221.5 3038.5,3221.5 3145.25,3221.5 4622,3222.25 4728.75,3222.25 4835.5,3222.25 4942.25,3222.25 5049,3222.25 2029.73,3241.14 2029.73,3292.14 4622,3329 4728.75,3329 4835.5,3329 4942.25,3329 5049,3329 2029.73,3343.14 2029.73,3414.14 2029.73,3465.14 2029.73,3516.14 2029.73,3567.14
NetC11_2: C11.2 R25.1 R26.1 | length 1612.5
  Mid-Layer 2 w10: v1(1962,3038) 1966,3034 1966,2984.3 2040.3,2910 2738,2910 2964,2684 v1(2964,2350)
  Bottom Layer w10: R26.1@1945,3071 1962,3054 v1(1962,3038) ; C11.2@2964,2321 2964,2369 R25.1@2973,2378
NetC19_2: C19.2 U2.32 | length 98.9
  Top Layer w10: C19.2@2309,2459 2332,2459 2339.41,2466.41 U2.32@2404.85,2466.41
NetC20_2: C20.2 C31.2 U2.49 U3.49 | length 1355.5
  Top Layer w10: U3.49@1736.95,2274.48 1736.95,2214.05 C31.2@1750,2201 1750,2188 v1(1762,2176) ; U2.49@2710.95,2274.48 2710.95,2216.05 C20.2@2722,2205
  Top Layer w15: v1(2722,2181) C20.2@2722,2205
  Mid-Layer 2 w10: v1(1762,2176) 1762,2135 1845,2052 2695,2052 2722,2079 v1(2722,2181)
NetC30_2: C30.2 U3.32 | length 98.9
  Top Layer w10: C30.2@1335,2459 1358,2459 1365.41,2466.41 U3.32@1430.85,2466.41
NetC37_1: C37.1 R44.2 R46.1 U4.1 | length 188.5
  Top Layer w9: v1(1202.5,965) 1211.48,956.02 U4.1@1224.91,956.02
  Bottom Layer w10: R46.1@1098.5,924 1098.5,972 R44.2@1107.5,981 1160.5,981 1186.5,981 v1(1202.5,965)
NetC43_1: C43.1 R49.2 R51.1 U5.1 | length 188.5
  Top Layer w9: v1(2690.67,965) 2699.64,956.02 U5.1@2713.08,956.02
  Bottom Layer w10: R51.1@2586.67,924 2586.67,972 R49.2@2595.67,981 C43.1@2648.67,981 2674.67,981 v1(2690.67,965)
NetC49_1: C49.1 R54.1 R56.2 U6.1 | length 188.5
  Top Layer w9: v1(1946.58,965) 1955.56,956.02 U6.1@1969,956.02
  Bottom Layer w10: R56.2@1842.58,924 1842.58,972 R54.1@1851.58,981 C49.1@1904.58,981 1930.58,981 v1(1946.58,965)
NetC55_1: C55.1 R59.1 R61.2 U7.1 | length 188.5
  Top Layer w9: v1(5667,965) 5675.98,956.02 U7.1@5689.41,956.02
  Bottom Layer w10: R61.2@5563,924 5563,972 R59.1@5572,981 C55.1@5625,981 5651,981 v1(5667,965)
NetC61_1: C61.1 R64.2 R66.1 U8.1 | length 188.5
  Top Layer w9: v1(4922.92,965) 4931.89,956.02 U8.1@4945.33,956.02
  Bottom Layer w10: R66.1@4818.92,924 4818.92,972 R64.2@4827.92,981 4880.92,981 4906.92,981 v1(4922.92,965)
NetC67_1: C67.1 R69.2 R71.1 U9.1 | length 188.5
  Top Layer w9: v1(3434.75,965) 3443.73,956.02 U9.1@3457.16,956.02
  Bottom Layer w10: R71.1@3330.75,924 3330.75,972 R69.2@3339.75,981 C67.1@3392.75,981 3418.75,981 v1(3434.75,965)
NetC73_1: C73.1 R74.1 R76.2 U10.1 | length 188.5
  Top Layer w9: v1(4178.83,965) 4187.81,956.02 U10.1@4201.25,956.02
  Bottom Layer w10: R76.2@4074.83,924 4074.83,972 4083.83,981 C73.1@4136.83,981 4162.83,981 v1(4178.83,965)
NetC78_1: C78.1 R79.2 R84.2 U11.4 | length 199
  Top Layer w10: U11.4@5715.62,2369.22 v1(5747.6,2369.22)
  Bottom Layer w10: v1(5747.6,2369.22) 5788.78,2369.22 R84.2@5795,2363 5853,2363 C78.1@5853,2304
NetC78_2: C78.2 R79.1 R80.2 | length 1103.3
  Mid-Layer 4 w10: v1(5593,3188) 5576,3171 5576,3073 5850,2799 5850,2362 5872,2340 v1(5902,2340)
  Bottom Layer w10: R80.2@5593,3159 v1(5593,3188) ; C78.2@5903,2304 5903,2348 R79.1@5919,2364
NetC83_2: C83.2 R77.1 R81.2 R82.2 R83.2 U11.6 U11.26 | length 983.7
  Top Layer w10: v2(5383.58,2471.58) U11.26@5418.38,2471.58 ; U11.6@5715.62,2420.4 5752.4,2420.4 v2(5760,2428)
  Mid-Layer 2 w20: v2(5383.58,2471.58) 5716.42,2471.58 v2(5760,2428)
  Bottom Layer w10: R83.2@5284,2291 5306,2313 5306,2383 5327,2404 R81.2@5347,2404 5347,2435 v2(5383.58,2471.58) 5422,2433.16 5450.84,2433.16 5475,2409 R77.1@5475,2331
  Bottom Layer w20: v2(5760,2428) 5760,2460 5777,2477 C83.2@5799,2477
NetC88_2: C88.2 U11.44 | length 66.1
  Top Layer w10: U11.44@5677.24,2271.78 5677.24,2230.76 C88.2@5695,2213
NetC89_2: C89.2 U11.27 | length 86.9
  Top Layer w9: 5369.01,2445.99 U11.27@5418.38,2445.99
  Top Layer w15: C89.2@5336,2457 5347.01,2445.99 5369.01,2445.99
NetC95_1: C95.1 R88.1 R90.2 U12.1 | length 188.5
  Top Layer w9: U12.1@6215.09,2286.81 6228.52,2286.81 v1(6237.5,2277.83)
  Bottom Layer w10: v1(6237.5,2277.83) 6253.5,2261.83 C95.1@6279.5,2261.83 6332.5,2261.83 6341.5,2270.83 R90.2@6341.5,2318.83
NetC106_1: C106.1 R93.2 R98.1 U13.4 | length 207.4
  Top Layer w10: U13.4@4036.15,2389.64 v1(4081.82,2389.64)
  Bottom Layer w10: v1(4081.82,2389.64) 4114.36,2389.64 R98.1@4125,2379 4176,2379 R93.2@4177,2380 4186,2371 C106.1@4186,2322
NetC106_2: C106.2 R93.1 R94.2 | length 1233.5
  Mid-Layer 4 w10: v1(3852,3341) 3866,3327 3866,3203.3 4236,2833.3 v1(4236,2354)
  Bottom Layer w10: R94.2@3852,3312 v1(3852,3341) ; C106.2@4236,2322 4236,2379 R93.1@4237,2380
NetC107_2: C107.2 R91.2 R95.2 R96.2 R97.1 U13.6 U13.31 | length 1002.8
  Top Layer w10: v2(3632,2492) U13.31@3679.85,2492 ; U13.6@4036.15,2440.82 v2(4084,2440.82)
  Mid-Layer 2 w20: v2(3632,2492) 4032.82,2492 v2(4084,2440.82)
  Bottom Layer w20: R95.2@3546,2430 3573,2457 R96.2@3601,2457 3601,2461 v2(3632,2492) 3675,2449 R97.1@3675,2399 3690,2399 3731,2358 R91.2@3731,2319 ; v2(4084,2440.82) 4084,2484 4103,2503 C107.2@4130,2503
NetC112_2: C112.2 U13.49 | length 83.7
  Top Layer w10: U13.49@3985.95,2274.48 3985.95,2212.05 C112.2@4001,2197
NetC113_2: C113.2 U13.32 | length 98.9
  Top Layer w10: C113.2@3584,2459 3607,2459 3614.41,2466.41 U13.32@3679.85,2466.41
NetC119_1: C119.1 R102.1 R104.1 R105.2 | length 179.2
  Bottom Layer w9: R102.1@4531,2221 4589,2221 C119.1@4590,2222 4590,2277 R104.1@4592,2279 R105.2@4592,2341
NetD1_1: D1.1 R18.2 | length 79
  Top Layer w15: R18.2@136,3273 D1.1@136,3352
NetD2_1: D2.1 R19.2 | length 79
  Top Layer w15: R19.2@284,3273 D2.1@284,3352
NetD3_1: D3.1 R20.2 | length 79
  Top Layer w15: R20.2@433,3272 D3.1@433,3351
NetD4_1: D4.1 R21.2 | length 79
  Top Layer w15: R21.2@579,3270 D4.1@579,3349
NetQ1_3: Q1.3 R18.1 | length 55
  Top Layer w15: Q1.3@196,3218 R18.1@196,3273
NetQ2_3: Q2.3 R19.1 | length 55
  Top Layer w15: Q2.3@344,3218 R19.1@344,3273
NetQ3_3: Q3.3 R20.1 | length 55
  Top Layer w15: Q3.3@493,3217 R20.1@493,3272
NetQ4_3: Q4.3 R21.1 | length 55
  Top Layer w15: Q4.3@639,3215 R21.1@639,3270
NetR2_2: R2.2 UAUX1.17 | length 67.9
  Bottom Layer w8: R2.2@543,2217 549,2217 578.78,2246.78 UAUX1.17@578.78,2266.54
NetR3_1: R3.1 R6.2 R8.2 | length 103
  Bottom Layer w10: R3.1@378,2299 431,2299 R8.2@431,2349
NetR6_1: R6.1 UAUX1.1 | length 58.6
  Bottom Layer w10: R6.1@493,2301 493.98,2301.98 UAUX1.1@551.22,2301.98
NetR9_1: R9.1 U1.12 | length 208.4
  Bottom Layer w6: U1.12@553.51,2808.13 617.13,2808.13 687,2878 R9.1@687,2924
NetR10_2: R10.2 U1.2 | length 484.3
  Bottom Layer w6: R10.2@206,2924 206,2822 277,2751 516,2751 530.87,2765.87 U1.2@530.87,2787.75
NetR11_2: R11.2 U1.3 | length 395.4
  Bottom Layer w6: R11.2@259.44,2924 259.44,2825.56 319,2766 506.27,2766 515.13,2774.85 U1.3@515.13,2787.75
NetR12_2: R12.2 U1.4 | length 295.6
  Bottom Layer w6: R12.2@312.89,2924 312.89,2834.11 359.25,2787.75 U1.4@499.38,2787.75
NetR13_2: R13.2 U1.6 | length 158
  Bottom Layer w6: R13.2@419.78,2924 419.78,2849.22 445.13,2823.87 U1.6@492.49,2823.87
NetR14_2: R14.2 U1.5 | length 219.5
  Bottom Layer w6: R14.2@366.33,2924 366.33,2846.67 404.87,2808.13 U1.5@492.49,2808.13
NetR15_1: R15.1 U1.10 | length 93.6
  Bottom Layer w6: U1.10@546.62,2844.23 546.62,2864.62 580.11,2898.11 R15.1@580.11,2924
NetR16_1: R16.1 U1.9 | length 79.8
  Bottom Layer w6: U1.9@530.87,2844.23 R16.1@530.87,2924
NetR17_1: R17.1 U1.8 | length 97.1
  Bottom Layer w6: R17.1@473.22,2924 473.22,2899.78 515.13,2857.87 U1.8@515.13,2844.23
NetR34_1: R34.1 U2.48 | length 75.1
  Top Layer w10: v1(2685.36,2228.81) U2.48@2685.36,2274.48
  Bottom Layer w10: v1@2685.55,2229 R34.1@2715,2229
NetR35_2: R35.2 U2.40 U3.41 | length 1137.3
  Top Layer w10: v1(1506.64,2228.81) U3.41@1506.64,2274.48 ; v1(2455.05,2228.81) U2.40@2455.05,2274.48
  Mid-Layer 4 w10: v1(1506.64,2228.81) 1506.64,2208.36 1514,2201 2427.24,2201 v1(2455.05,2228.81)
  Bottom Layer w10: R35.2@2410,2271 2452.19,2228.81 v1(2455.05,2228.81)
NetR37_2: R37.2 R38.2 U3.37 | length 197.4
  Top Layer w10: v1(1385.18,2338.46) U3.37@1430.85,2338.46
  Bottom Layer w10: R38.2@1340,2315 1361.72,2315 v1(1385.18,2338.46) R37.2@1482,2338.46
NetR39_2: R39.2 U3.36 | length 93.3
  Top Layer w10: v1(1385.18,2364.05) U3.36@1430.85,2364.05
  Bottom Layer w10: R39.2@1340,2370 1345.95,2364.05 v1(1385.18,2364.05)
NetR40_2: R40.2 U3.48 | length 79.8
  Top Layer w10: v1(1711.36,2228.81) U3.48@1711.36,2274.48
  Bottom Layer w10: v1(1711.36,2228.81) 1743.81,2228.81 R40.2@1745,2230
NetR41_1: R41.1 U3.40 | length 76.9
  Top Layer w10: v1(1481.05,2228.81) U3.40@1481.05,2274.48
  Bottom Layer w10: R41.1@1449.81,2228.81 v1(1481.05,2228.81)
